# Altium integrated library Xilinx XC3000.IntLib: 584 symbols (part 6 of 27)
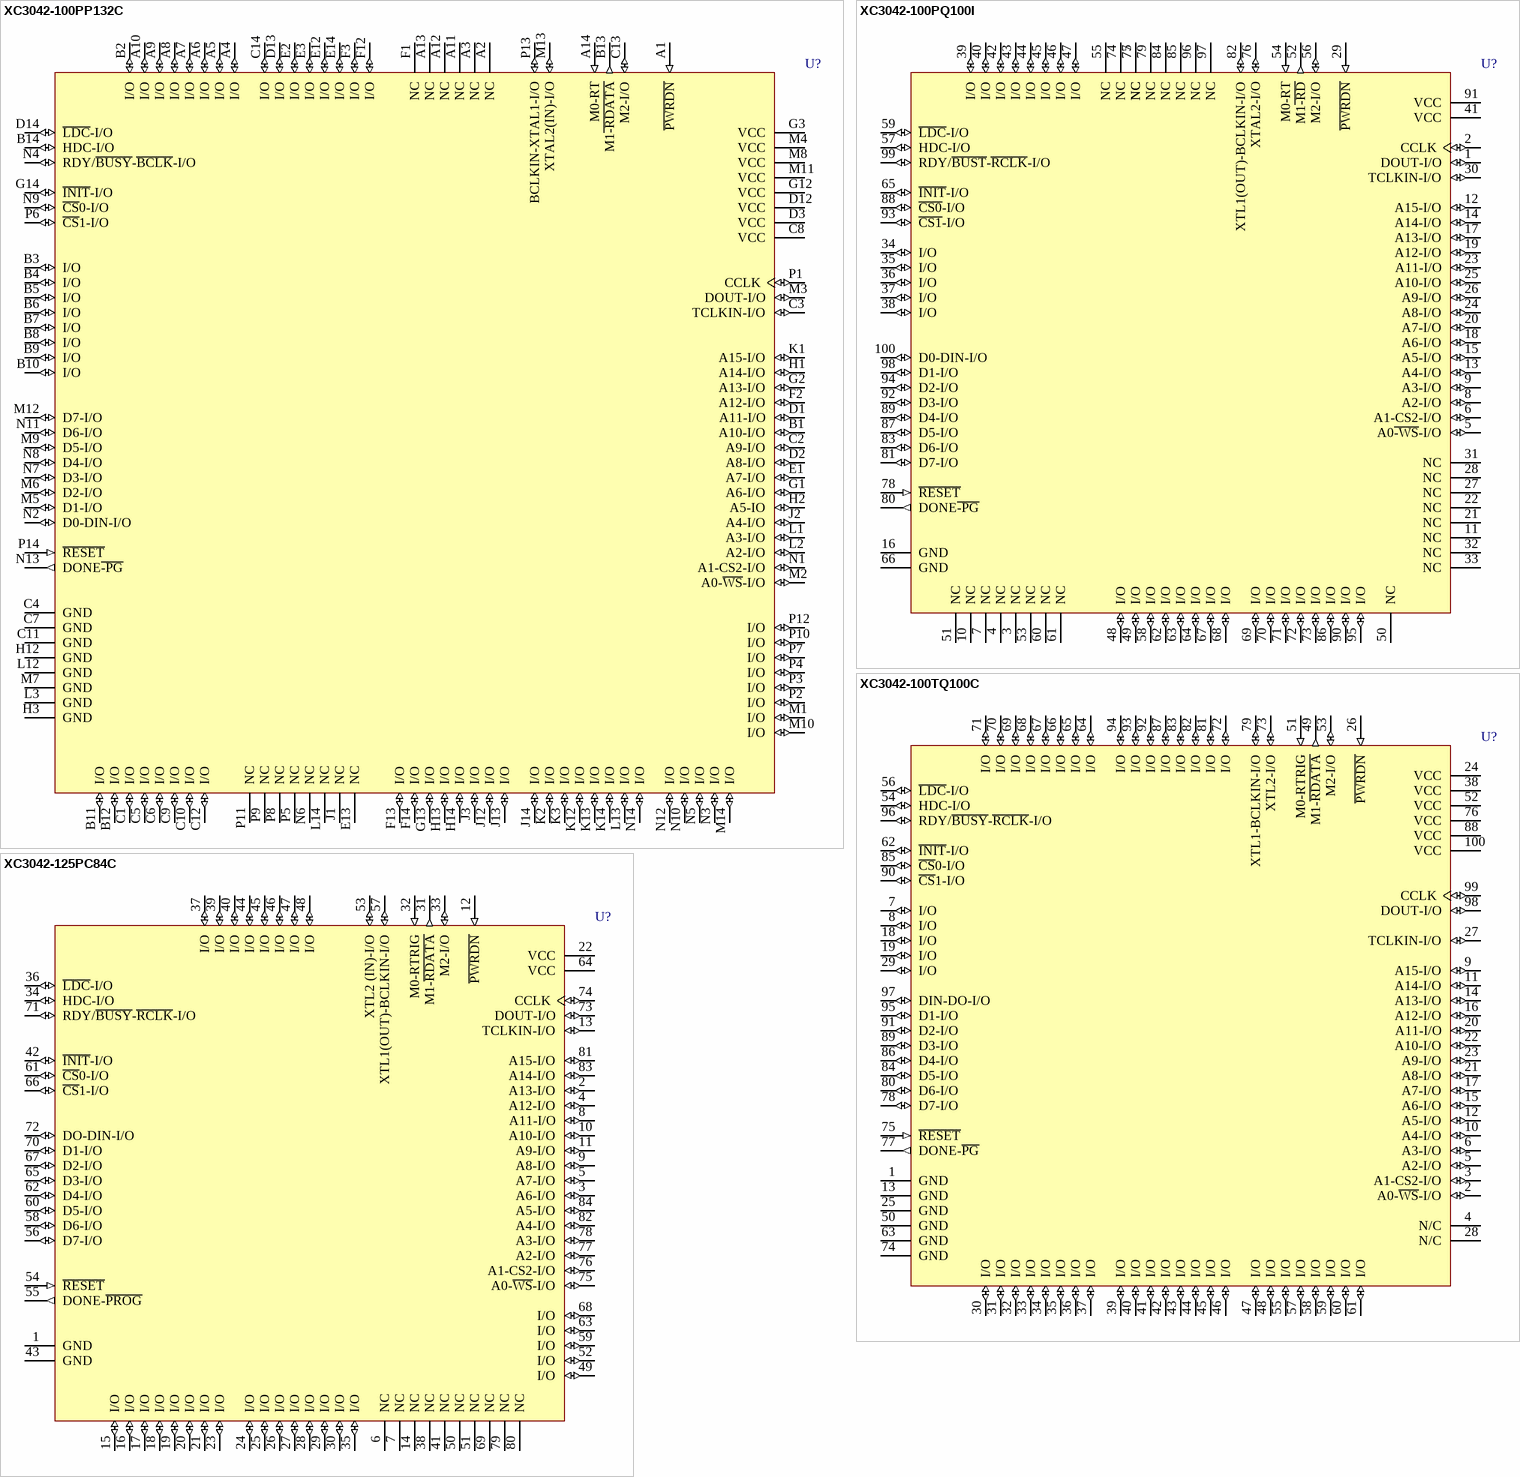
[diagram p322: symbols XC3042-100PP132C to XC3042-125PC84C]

## XC3042-100TQ100C
designator U?
Logic Cell Array with 144 CLBs, with 80 I/O Pins, 100-Pin TQFP, Commercial Grade; ComponentAvailability: Not for New Design
footprint TQ100_N (Thin QFP, 100-Leads, Body 14x14mm, Pitch 0.5mm, IPC Medium Density)
footprint TQ100_L (Thin QFP, 100-Leads, Body 14x14mm, Pitch 0.5mm, IPC High Density)
footprint TQ100_M (Thin QFP, 100-Leads, Body 14x14mm, Pitch 0.5mm, IPC Low Density)
3D model XC3042-TQ100 (100-Pin Thin Quad Flat Pack (TQ100))
pins: 1 GND (power), 2 A0-~{WS}-I/O (io), 3 A1-CS2-I/O (io), 4 N/C, 5 A2-I/O (io), 6 A3-I/O (io), 7 I/O (io), 8 I/O (io), 9 A15-I/O (io), 10 A4-I/O (io), 11 A14-I/O (io), 12 A5-I/O (io), 13 GND (power), 14 A13-I/O (io), 15 A6-I/O (io), 16 A12-I/O (io), 17 A7-I/O (io), 18 I/O (io), 19 I/O (io), 20 A11-I/O (io), 21 A8-I/O (io), 22 A10-I/O (io), 23 A9-I/O (io), 24 VCC (power), 25 GND (power), 26 ~{PWRDN} (in), 27 TCLKIN-I/O (io), 28 N/C, 29 I/O (io), 30 I/O (io), 31 I/O (io), 32 I/O (io), 33 I/O (io), 34 I/O (io), 35 I/O (io), 36 I/O (io), 37 I/O (io), 38 VCC (power), 39 I/O (io), 40 I/O (io), 41 I/O (io), 42 I/O (io), 43 I/O (io), 44 I/O (io), 45 I/O (io), 46 I/O (io), 47 I/O (io), 48 I/O (io), 49 M1-~{RDATA} (out), 50 GND (power), 51 M0-RTRIG (in), 52 VCC (power), 53 M2-I/O (io), 54 HDC-I/O (io), 55 I/O (io), 56 ~{LDC}-I/O (io), 57 I/O (io), 58 I/O (io), 59 I/O (io), 60 I/O (io), 61 I/O (io), 62 ~{INIT}-I/O (io), 63 GND (power), 64 I/O (io), 65 I/O (io), 66 I/O (io), 67 I/O (io), 68 I/O (io), 69 I/O (io), 70 I/O (io), 71 I/O (io), 72 I/O (io), 73 XTL2-I/O (io), 74 GND (power), 75 ~{RESET} (in), 76 VCC (power), 77 DONE-~{PG} (out), 78 D7-I/O (io), 79 XTL1-BCLKIN-I/O (io), 80 D6-I/O (io), 81 I/O (io), 82 I/O (io), 83 I/O (io), 84 D5-I/O (io), 85 ~{CS}0-I/O (io), 86 D4-I/O (io), 87 I/O (io), 88 VCC (power), 89 D3-I/O (io), 90 ~{CS}1-I/O (io), 91 D2-I/O (io), 92 I/O (io), 93 I/O (io), 94 I/O (io), 95 D1-I/O (io), 96 RDY/~{BUSY}-~{RCLK}-I/O (io), 97 DIN-DO-I/O (io), 98 DOUT-I/O (io), 99 CCLK (io), 100 VCC (power)

## XC3042-125PC84C
designator U?
Logic Cell Array with 144 CLBs, with 64 I/O Pins, 84-Pin PLCC, Commercial Grade; ComponentAvailability: Not for New Design
footprint PC84_N (Leaded Chip Carrier, 84-Leads, Body 29.3x29.3mm, Pitch 1.27mm, IPC Medium Density)
footprint PC84_L (Leaded Chip Carrier, 84-Leads, Body 29.3x29.3mm, Pitch 1.27mm, IPC High Density)
footprint PC84_M (Leaded Chip Carrier, 84-Leads, Body 29.3x29.3mm, Pitch 1.27mm, IPC Low Density)
3D model XC3042-PC84 (84-Pin Plastic Leaded Chip Carrier (PC84))
pins: 1 GND (power), 2 A13-I/O (io), 3 A6-I/O (io), 4 A12-I/O (io), 5 A7-I/O (io), 6 NC, 7 NC, 8 A11-I/O (io), 9 A8-I/O (io), 10 A10-I/O (io), 11 A9-I/O (io), 12 ~{PWRDN} (in), 13 TCLKIN-I/O (io), 14 NC, 15 I/O (io), 16 I/O (io), 17 I/O (io), 18 I/O (io), 19 I/O (io), 20 I/O (io), 21 I/O (io), 22 VCC (power), 23 I/O (io), 24 I/O (io), 25 I/O (io), 26 I/O (io), 27 I/O (io), 28 I/O (io), 29 I/O (io), 30 I/O (io), 31 M1-~{RDATA} (out), 32 M0-RTRIG (in), 33 M2-I/O (io), 34 HDC-I/O (io), 35 I/O (io), 36 ~{LDC}-I/O (io), 37 I/O (io), 38 NC, 39 I/O (io), 40 I/O (io), 41 NC, 42 ~{INIT}-I/O (io), 43 GND (power), 44 I/O (io), 45 I/O (io), 46 I/O (io), 47 I/O (io), 48 I/O (io), 49 I/O (io), 50 NC, 51 NC, 52 I/O (io), 53 XTL2 (IN)-I/O (io), 54 ~{RESET} (in), 55 DONE-~{PROG} (out), 56 D7-I/O (io), 57 XTL1(OUT)-BCLKIN-I/O (io), 58 D6-I/O (io), 59 I/O (io), 60 D5-I/O (io), 61 ~{CS}0-I/O (io), 62 D4-I/O (io), 63 I/O (io), 64 VCC (power), 65 D3-I/O (io), 66 ~{CS}1-I/O (io), 67 D2-I/O (io), 68 I/O (io), 69 NC, 70 D1-I/O (io), 71 RDY/~{BUSY}-~{RCLK}-I/O (io), 72 DO-DIN-I/O (io), 73 DOUT-I/O (io), 74 CCLK (io), 75 A0-~{WS}-I/O (io), 76 A1-CS2-I/O (io), 77 A2-I/O (io), 78 A3-I/O (io), 79 NC, 80 NC, 81 A15-I/O (io), 82 A4-I/O (io), 83 A14-I/O (io), 84 A5-I/O (io)

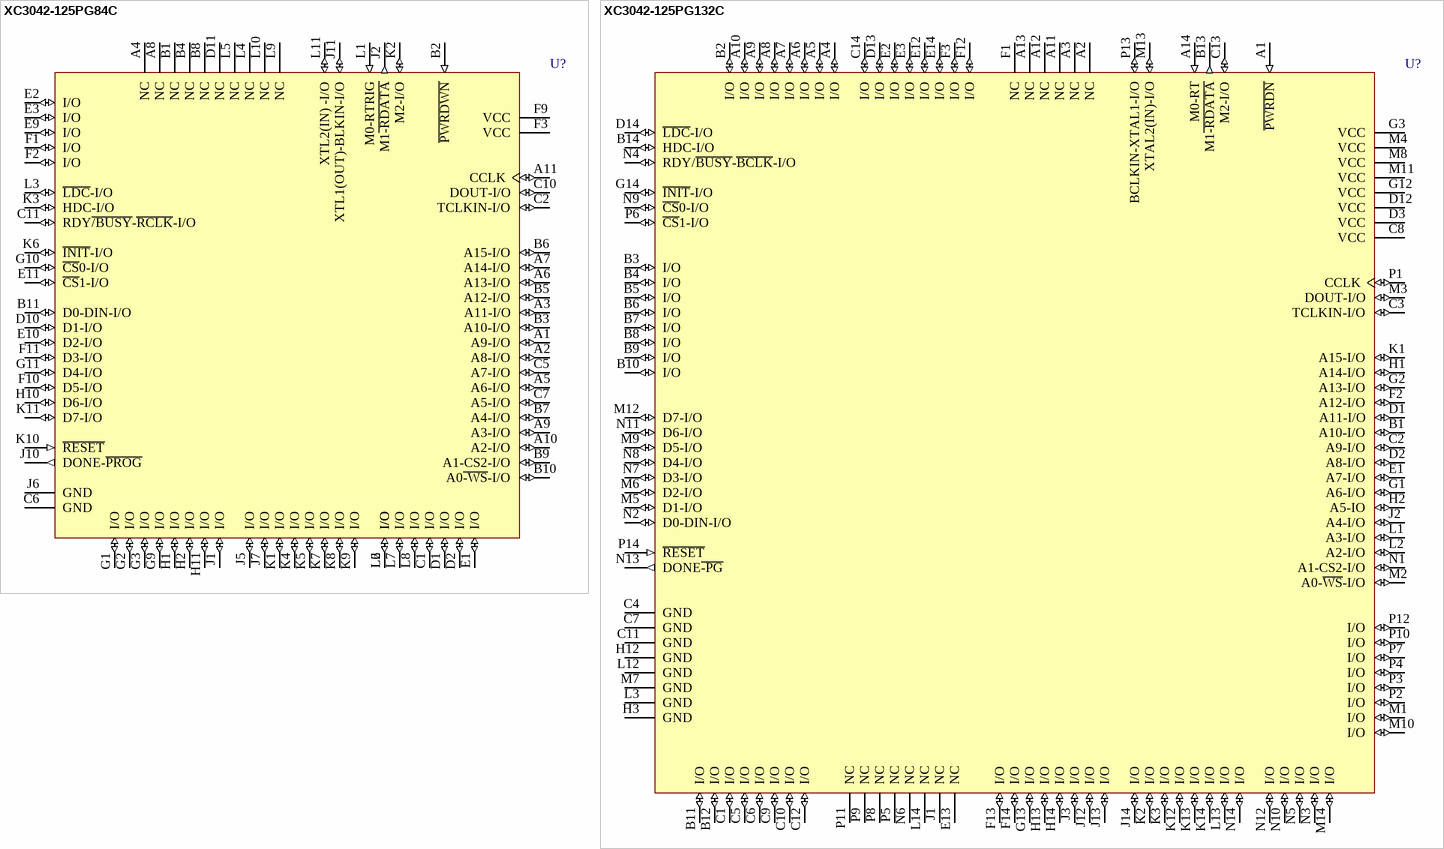
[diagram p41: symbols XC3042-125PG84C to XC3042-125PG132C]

## XC3042-125PG84C
designator U?
Logic Cell Array with 144 CLBs, with 64 I/O Pins, 84-Pin PGA, Commercial Grade; ComponentAvailability: Not for New Design
footprint PG84 (PGA, 85-Leads, Body 28x28mm, Pitch 2.54mm)
3D model XC3042-PG84 (84-Pin Ceramic Pin Grid Array (PG84))
pins: A1 A9-I/O (io), A2 A8-I/O (io), A3 A11-I/O (io), A4 NC, A5 A6-I/O (io), A6 A13-I/O (io), A7 A14-I/O (io), A8 NC, A9 A3-I/O (io), A10 A2-I/O (io), A11 CCLK (io), B1 NC, B2 ~{PWRDWN} (in), B3 A10-I/O (io), B4 NC, B5 A12-I/O (io), B6 A15-I/O (io), B7 A4-I/O (io), B8 NC, B9 A1-CS2-I/O (io), B10 A0~{-WS}-I/O (io), B11 D0-DIN-I/O (io), C1 I/O (io), C2 TCLKIN-I/O (io), C5 A7-I/O (io), C6 GND (power), C7 A5-I/O (io), C10 DOUT-I/O (io), C11 RDY~{/BUSY}-~{RCLK}-I/O (io), D1 I/O (io), D2 I/O (io), D10 D1-I/O (io), D11 NC, E1 I/O (io), E2 I/O (io), E3 I/O (io), E9 I/O (io), E10 D2-I/O (io), E11 ~{CS}1-I/O (io), F1 I/O (io), F2 I/O (io), F3 VCC (power), F9 VCC (power), F10 D5-I/O (io), F11 D3-I/O (io), G1 I/O (io), G2 I/O (io), G3 I/O (io), G9 I/O (io), G10 ~{CS}0-I/O (io), G11 D4-I/O (io), H1 I/O (io), H2 I/O (io), H10 D6-I/O (io), H11 I/O (io), J1 I/O (io), J2 M1~{-RDATA} (out), J5 I/O (io), J6 GND (power), J7 I/O (io), J10 DONE-~{PROG} (out), J11 XTL1(OUT)-BLKIN-I/O (io), K1 I/O (io), K2 M2-I/O (io), K3 HDC-I/O (io), K4 I/O (io), K5 I/O (io), K6 ~{INIT}-I/O (io), K7 I/O (io), K8 I/O (io), K9 I/O (io), K10 ~{RESET} (in), K11 D7-I/O (io), L1 M0-RTRIG (in), L2 I/O (io), L3 ~{LDC}-I/O (io), L4 NC, L5 NC, L6 I/O (io), L7 I/O (io), L8 I/O (io), L9 NC, L10 NC, L11 XTL2(IN) -I/O (io)

## XC3042-125PG132C
designator U?
Logic Cell Array with 144 CLBs, with 96 I/O Pins, 132-Pin PGA, Commercial Grade; ComponentAvailability: Not for New Design
footprint PG132 (PGA, 132-Leads, Body 37x37mm, Pitch 2.54mm)
3D model XC3042-PG132 (132-Pin Ceramic Pin Grid Array (PG132))
pins: A1 ~{PWRDN} (in), A2 NC, A3 NC, A4 I/O (io), A5 I/O (io), A6 I/O (io), A7 I/O (io), A8 I/O (io), A9 I/O (io), A10 I/O (io), A11 NC, A12 NC, A13 NC, A14 M0-RT (in), B1 A10-I/O (io), B2 I/O (io), B3 I/O (io), B4 I/O (io), B5 I/O (io), B6 I/O (io), B7 I/O (io), B8 I/O (io), B9 I/O (io), B10 I/O (io), B11 I/O (io), B12 I/O (io), B13 M1~{-RDATA} (out), B14 HDC-I/O (io), C1 I/O (io), C2 A9-I/O (io), C3 TCLKIN-I/O (io), C4 GND (power), C5 I/O (io), C6 I/O (io), C7 GND (power), C8 VCC (power), C9 I/O (io), C10 I/O (io), C11 GND (power), C12 I/O (io), C13 M2-I/O (io), C14 I/O (io), D1 A11-I/O (io), D2 A8-I/O (io), D3 VCC (power), D12 VCC (power), D13 I/O (io), D14 ~{LDC}-I/O (io), E1 A7-I/O (io), E2 I/O (io), E3 I/O (io), E12 I/O (io), E13 NC, E14 I/O (io), F1 NC, F2 A12-I/O (io), F3 I/O (io), F12 I/O (io), F13 I/O (io), F14 I/O (io), G1 A6-I/O (io), G2 A13-I/O (io), G3 VCC (power), G12 VCC (power), G13 I/O (io), G14 ~{INIT}-I/O (io), H1 A14-I/O (io), H2 A5-IO (io), H3 GND (power), H12 GND (power), H13 I/O (io), H14 I/O (io), J1 NC, J2 A4-I/O (io), J3 I/O (io), J12 I/O (io), J13 I/O (io), J14 I/O (io), K1 A15-I/O (io), K2 I/O (io), K3 I/O (io), K12 I/O (io), K13 I/O (io), K14 I/O (io), L1 A3-I/O (io), L2 A2-I/O (io), L3 GND (power), L12 GND (power), L13 I/O (io), L14 NC, M1 I/O (io), M2 A0-~{WS}-I/O (io), M3 DOUT-I/O (io), M4 VCC (power), M5 D1-I/O (io), M6 D2-I/O (io), M7 GND (power), M8 VCC (power), M9 D5-I/O (io), M10 I/O (io), M11 VCC (power), M12 D7-I/O (io), M13 XTAL2(IN)-I/O (io), M14 I/O (io), N1 A1-CS2-I/O (io), N2 D0-DIN-I/O (io), N3 I/O (io), N4 RDY/~{BUSY}-~{BCLK}-I/O (io), N5 I/O (io), N6 NC, N7 D3-I/O (io), N8 D4-I/O (io), N9 ~{CS}0-I/O (io), N10 I/O (io), N11 D6-I/O (io), N12 I/O (io), N13 DONE~{-PG} (out), N14 I/O (io), P1 CCLK (io), P2 I/O (io), P3 I/O (io), P4 I/O (io), P5 NC, P6 ~{CS}1-I/O (io), P7 I/O (io), P8 NC, P9 NC, P10 I/O (io), P11 NC, P12 I/O (io), P13 BCLKIN-XTAL1-I/O (io), P14 ~{RESET} (in)

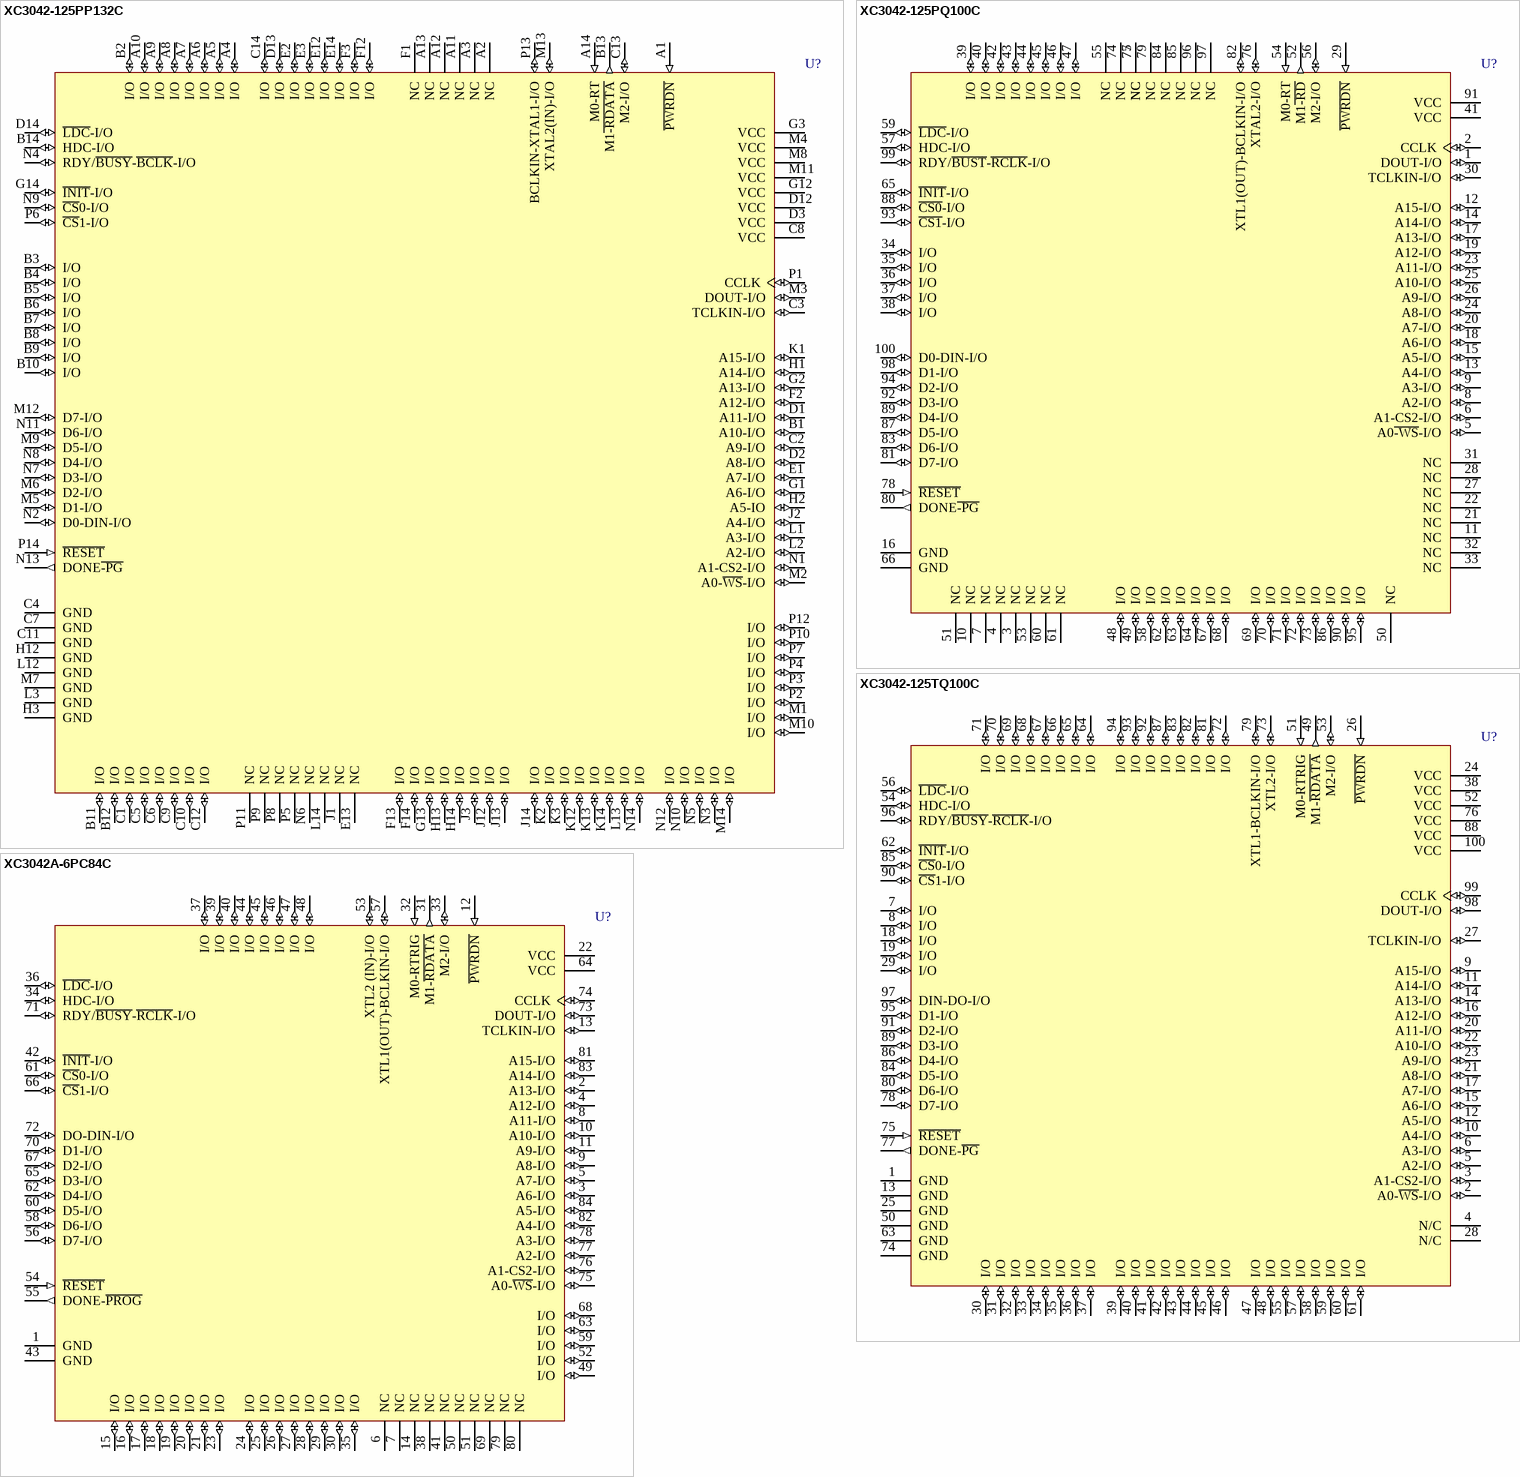
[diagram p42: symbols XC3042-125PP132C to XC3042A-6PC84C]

## XC3042-125PP132C
designator U?
Logic Cell Array with 144 CLBs, with 96 I/O Pins, 132-Pin PGA, Commercial Grade; ComponentAvailability: Not for New Design
footprint PP132 (PGA, 132-Leads, Body 37x37mm, Pitch 2.54mm)
3D model XC3042-PP132 (132-Pin Plastic Pin Grid Array (PP132))
pins: A1 ~{PWRDN} (in), A2 NC, A3 NC, A4 I/O (io), A5 I/O (io), A6 I/O (io), A7 I/O (io), A8 I/O (io), A9 I/O (io), A10 I/O (io), A11 NC, A12 NC, A13 NC, A14 M0-RT (in), B1 A10-I/O (io), B2 I/O (io), B3 I/O (io), B4 I/O (io), B5 I/O (io), B6 I/O (io), B7 I/O (io), B8 I/O (io), B9 I/O (io), B10 I/O (io), B11 I/O (io), B12 I/O (io), B13 M1~{-RDATA} (out), B14 HDC-I/O (io), C1 I/O (io), C2 A9-I/O (io), C3 TCLKIN-I/O (io), C4 GND (power), C5 I/O (io), C6 I/O (io), C7 GND (power), C8 VCC (power), C9 I/O (io), C10 I/O (io), C11 GND (power), C12 I/O (io), C13 M2-I/O (io), C14 I/O (io), D1 A11-I/O (io), D2 A8-I/O (io), D3 VCC (power), D12 VCC (power), D13 I/O (io), D14 ~{LDC}-I/O (io), E1 A7-I/O (io), E2 I/O (io), E3 I/O (io), E12 I/O (io), E13 NC, E14 I/O (io), F1 NC, F2 A12-I/O (io), F3 I/O (io), F12 I/O (io), F13 I/O (io), F14 I/O (io), G1 A6-I/O (io), G2 A13-I/O (io), G3 VCC (power), G12 VCC (power), G13 I/O (io), G14 ~{INIT}-I/O (io), H1 A14-I/O (io), H2 A5-IO (io), H3 GND (power), H12 GND (power), H13 I/O (io), H14 I/O (io), J1 NC, J2 A4-I/O (io), J3 I/O (io), J12 I/O (io), J13 I/O (io), J14 I/O (io), K1 A15-I/O (io), K2 I/O (io), K3 I/O (io), K12 I/O (io), K13 I/O (io), K14 I/O (io), L1 A3-I/O (io), L2 A2-I/O (io), L3 GND (power), L12 GND (power), L13 I/O (io), L14 NC, M1 I/O (io), M2 A0-~{WS}-I/O (io), M3 DOUT-I/O (io), M4 VCC (power), M5 D1-I/O (io), M6 D2-I/O (io), M7 GND (power), M8 VCC (power), M9 D5-I/O (io), M10 I/O (io), M11 VCC (power), M12 D7-I/O (io), M13 XTAL2(IN)-I/O (io), M14 I/O (io), N1 A1-CS2-I/O (io), N2 D0-DIN-I/O (io), N3 I/O (io), N4 RDY/~{BUSY}-~{BCLK}-I/O (io), N5 I/O (io), N6 NC, N7 D3-I/O (io), N8 D4-I/O (io), N9 ~{CS}0-I/O (io), N10 I/O (io), N11 D6-I/O (io), N12 I/O (io), N13 DONE~{-PG} (out), N14 I/O (io), P1 CCLK (io), P2 I/O (io), P3 I/O (io), P4 I/O (io), P5 NC, P6 ~{CS}1-I/O (io), P7 I/O (io), P8 NC, P9 NC, P10 I/O (io), P11 NC, P12 I/O (io), P13 BCLKIN-XTAL1-I/O (io), P14 ~{RESET} (in)

## XC3042-125PQ100C
designator U?
Logic Cell Array with 144 CLBs, with 64 I/O Pins, 100-Pin PQFP, Commercial Grade; ComponentAvailability: Not for New Design
footprint PQ100_N (QFP, 100-Leads, Body 20x14mm, Pitch 0.65mm, IPC Medium Density)
footprint PQ100_L (QFP, 100-Leads, Body 20x14mm, Pitch 0.65mm, IPC High Density)
footprint PQ100_M (QFP, 100-Leads, Body 20x14mm, Pitch 0.65mm, IPC Low Density)
3D model XC3042-PQ100 (100-Pin Plastic Quad Flat Pack (PQ100))
pins: 1 DOUT-I/O (io), 2 CCLK (io), 3 NC, 4 NC, 5 A0~{-WS}-I/O (io), 6 A1-CS2-I/O (io), 7 NC, 8 A2-I/O (io), 9 A3-I/O (io), 10 NC, 11 NC, 12 A15-I/O (io), 13 A4-I/O (io), 14 A14-I/O (io), 15 A5-I/O (io), 16 GND (power), 17 A13-I/O (io), 18 A6-I/O (io), 19 A12-I/O (io), 20 A7-I/O (io), 21 NC, 22 NC, 23 A11-I/O (io), 24 A8-I/O (io), 25 A10-I/O (io), 26 A9-I/O (io), 27 NC, 28 NC, 29 ~{PWRDN} (in), 30 TCLKIN-I/O (io), 31 NC, 32 NC, 33 NC, 34 I/O (io), 35 I/O (io), 36 I/O (io), 37 I/O (io), 38 I/O (io), 39 I/O (io), 40 I/O (io), 41 VCC (power), 42 I/O (io), 43 I/O (io), 44 I/O (io), 45 I/O (io), 46 I/O (io), 47 I/O (io), 48 I/O (io), 49 I/O (io), 50 NC, 51 NC, 52 M1~{-RD} (out), 53 NC, 54 M0-RT (in), 55 NC, 56 M2-I/O (io), 57 HDC-I/O (io), 58 I/O (io), 59 ~{LDC}-I/O (io), 60 NC, 61 NC, 62 I/O (io), 63 I/O (io), 64 I/O (io), 65 ~{INIT}-I/O (io), 66 GND (power), 67 I/O (io), 68 I/O (io), 69 I/O (io), 70 I/O (io), 71 I/O (io), 72 I/O (io), 73 I/O (io), 74 NC, 75 NC, 76 XTAL2-I/O (io), 77 NC, 78 ~{RESET} (in), 79 NC, 80 DONE~{-PG} (out), 81 D7-I/O (io), 82 XTL1(OUT)-BCLKIN-I/O (io), 83 D6-I/O (io), 84 NC, 85 NC, 86 I/O (io), 87 D5-I/O (io), 88 ~{CS0}-I/O (io), 89 D4-I/O (io), 90 I/O (io), 91 VCC (power), 92 D3-I/O (io), 93 ~{CS1}-I/O (io), 94 D2-I/O (io), 95 I/O (io), 96 NC, 97 NC, 98 D1-I/O (io), 99 RDY/~{BUST}-~{RCLK}-I/O (io), 100 D0-DIN-I/O (io)

## XC3042-125TQ100C
designator U?
Logic Cell Array with 144 CLBs, with 80 I/O Pins, 100-Pin TQFP, Commercial Grade; ComponentAvailability: Not for New Design
footprint TQ100_N (Thin QFP, 100-Leads, Body 14x14mm, Pitch 0.5mm, IPC Medium Density)
footprint TQ100_L (Thin QFP, 100-Leads, Body 14x14mm, Pitch 0.5mm, IPC High Density)
footprint TQ100_M (Thin QFP, 100-Leads, Body 14x14mm, Pitch 0.5mm, IPC Low Density)
3D model XC3042-TQ100 (100-Pin Thin Quad Flat Pack (TQ100))
pins: 1 GND (power), 2 A0-~{WS}-I/O (io), 3 A1-CS2-I/O (io), 4 N/C, 5 A2-I/O (io), 6 A3-I/O (io), 7 I/O (io), 8 I/O (io), 9 A15-I/O (io), 10 A4-I/O (io), 11 A14-I/O (io), 12 A5-I/O (io), 13 GND (power), 14 A13-I/O (io), 15 A6-I/O (io), 16 A12-I/O (io), 17 A7-I/O (io), 18 I/O (io), 19 I/O (io), 20 A11-I/O (io), 21 A8-I/O (io), 22 A10-I/O (io), 23 A9-I/O (io), 24 VCC (power), 25 GND (power), 26 ~{PWRDN} (in), 27 TCLKIN-I/O (io), 28 N/C, 29 I/O (io), 30 I/O (io), 31 I/O (io), 32 I/O (io), 33 I/O (io), 34 I/O (io), 35 I/O (io), 36 I/O (io), 37 I/O (io), 38 VCC (power), 39 I/O (io), 40 I/O (io), 41 I/O (io), 42 I/O (io), 43 I/O (io), 44 I/O (io), 45 I/O (io), 46 I/O (io), 47 I/O (io), 48 I/O (io), 49 M1-~{RDATA} (out), 50 GND (power), 51 M0-RTRIG (in), 52 VCC (power), 53 M2-I/O (io), 54 HDC-I/O (io), 55 I/O (io), 56 ~{LDC}-I/O (io), 57 I/O (io), 58 I/O (io), 59 I/O (io), 60 I/O (io), 61 I/O (io), 62 ~{INIT}-I/O (io), 63 GND (power), 64 I/O (io), 65 I/O (io), 66 I/O (io), 67 I/O (io), 68 I/O (io), 69 I/O (io), 70 I/O (io), 71 I/O (io), 72 I/O (io), 73 XTL2-I/O (io), 74 GND (power), 75 ~{RESET} (in), 76 VCC (power), 77 DONE-~{PG} (out), 78 D7-I/O (io), 79 XTL1-BCLKIN-I/O (io), 80 D6-I/O (io), 81 I/O (io), 82 I/O (io), 83 I/O (io), 84 D5-I/O (io), 85 ~{CS}0-I/O (io), 86 D4-I/O (io), 87 I/O (io), 88 VCC (power), 89 D3-I/O (io), 90 ~{CS}1-I/O (io), 91 D2-I/O (io), 92 I/O (io), 93 I/O (io), 94 I/O (io), 95 D1-I/O (io), 96 RDY/~{BUSY}-~{RCLK}-I/O (io), 97 DIN-DO-I/O (io), 98 DOUT-I/O (io), 99 CCLK (io), 100 VCC (power)

## XC3042A-6PC84C
designator U?
Logic Cell Array with 144 CLBs, with 64 I/O Pins, 84-Pin PLCC, Commercial Grade; ComponentAvailability: Not for New Design
footprint PC84_N (Leaded Chip Carrier, 84-Leads, Body 29.3x29.3mm, Pitch 1.27mm, IPC Medium Density)
footprint PC84_L (Leaded Chip Carrier, 84-Leads, Body 29.3x29.3mm, Pitch 1.27mm, IPC High Density)
footprint PC84_M (Leaded Chip Carrier, 84-Leads, Body 29.3x29.3mm, Pitch 1.27mm, IPC Low Density)
3D model XC3042A-PC84 (84-Pin Plastic Leaded Chip Carrier (PC84))
pins: 1 GND (power), 2 A13-I/O (io), 3 A6-I/O (io), 4 A12-I/O (io), 5 A7-I/O (io), 6 NC, 7 NC, 8 A11-I/O (io), 9 A8-I/O (io), 10 A10-I/O (io), 11 A9-I/O (io), 12 ~{PWRDN} (in), 13 TCLKIN-I/O (io), 14 NC, 15 I/O (io), 16 I/O (io), 17 I/O (io), 18 I/O (io), 19 I/O (io), 20 I/O (io), 21 I/O (io), 22 VCC (power), 23 I/O (io), 24 I/O (io), 25 I/O (io), 26 I/O (io), 27 I/O (io), 28 I/O (io), 29 I/O (io), 30 I/O (io), 31 M1-~{RDATA} (out), 32 M0-RTRIG (in), 33 M2-I/O (io), 34 HDC-I/O (io), 35 I/O (io), 36 ~{LDC}-I/O (io), 37 I/O (io), 38 NC, 39 I/O (io), 40 I/O (io), 41 NC, 42 ~{INIT}-I/O (io), 43 GND (power), 44 I/O (io), 45 I/O (io), 46 I/O (io), 47 I/O (io), 48 I/O (io), 49 I/O (io), 50 NC, 51 NC, 52 I/O (io), 53 XTL2 (IN)-I/O (io), 54 ~{RESET} (in), 55 DONE-~{PROG} (out), 56 D7-I/O (io), 57 XTL1(OUT)-BCLKIN-I/O (io), 58 D6-I/O (io), 59 I/O (io), 60 D5-I/O (io), 61 ~{CS}0-I/O (io), 62 D4-I/O (io), 63 I/O (io), 64 VCC (power), 65 D3-I/O (io), 66 ~{CS}1-I/O (io), 67 D2-I/O (io), 68 I/O (io), 69 NC, 70 D1-I/O (io), 71 RDY/~{BUSY}-~{RCLK}-I/O (io), 72 DO-DIN-I/O (io), 73 DOUT-I/O (io), 74 CCLK (io), 75 A0-~{WS}-I/O (io), 76 A1-CS2-I/O (io), 77 A2-I/O (io), 78 A3-I/O (io), 79 NC, 80 NC, 81 A15-I/O (io), 82 A4-I/O (io), 83 A14-I/O (io), 84 A5-I/O (io)

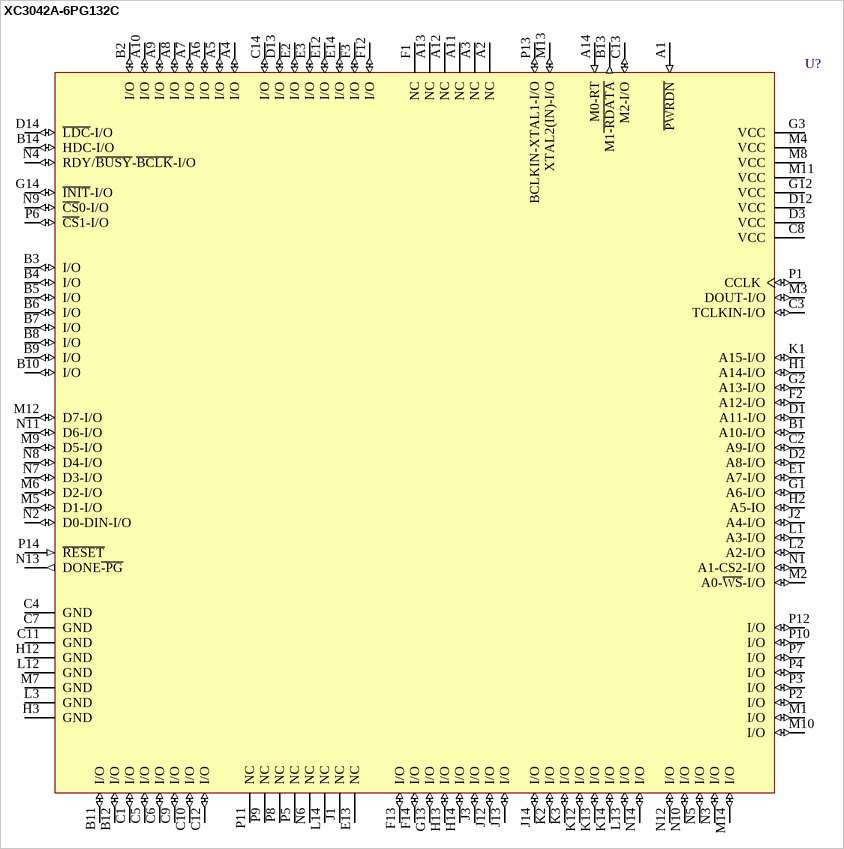
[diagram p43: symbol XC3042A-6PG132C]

## XC3042A-6PG132C
designator U?
Logic Cell Array with 144 CLBs, with 96 I/O Pins, 132-Pin PGA, Commercial Grade; ComponentAvailability: Not for New Design
footprint PG132 (PGA, 132-Leads, Body 37x37mm, Pitch 2.54mm)
3D model XC3042A-PG132 (132-Pin Ceramic Pin Grid Array (PG132))
pins: A1 ~{PWRDN} (in), A2 NC, A3 NC, A4 I/O (io), A5 I/O (io), A6 I/O (io), A7 I/O (io), A8 I/O (io), A9 I/O (io), A10 I/O (io), A11 NC, A12 NC, A13 NC, A14 M0-RT (in), B1 A10-I/O (io), B2 I/O (io), B3 I/O (io), B4 I/O (io), B5 I/O (io), B6 I/O (io), B7 I/O (io), B8 I/O (io), B9 I/O (io), B10 I/O (io), B11 I/O (io), B12 I/O (io), B13 M1~{-RDATA} (out), B14 HDC-I/O (io), C1 I/O (io), C2 A9-I/O (io), C3 TCLKIN-I/O (io), C4 GND (power), C5 I/O (io), C6 I/O (io), C7 GND (power), C8 VCC (power), C9 I/O (io), C10 I/O (io), C11 GND (power), C12 I/O (io), C13 M2-I/O (io), C14 I/O (io), D1 A11-I/O (io), D2 A8-I/O (io), D3 VCC (power), D12 VCC (power), D13 I/O (io), D14 ~{LDC}-I/O (io), E1 A7-I/O (io), E2 I/O (io), E3 I/O (io), E12 I/O (io), E13 NC, E14 I/O (io), F1 NC, F2 A12-I/O (io), F3 I/O (io), F12 I/O (io), F13 I/O (io), F14 I/O (io), G1 A6-I/O (io), G2 A13-I/O (io), G3 VCC (power), G12 VCC (power), G13 I/O (io), G14 ~{INIT}-I/O (io), H1 A14-I/O (io), H2 A5-IO (io), H3 GND (power), H12 GND (power), H13 I/O (io), H14 I/O (io), J1 NC, J2 A4-I/O (io), J3 I/O (io), J12 I/O (io), J13 I/O (io), J14 I/O (io), K1 A15-I/O (io), K2 I/O (io), K3 I/O (io), K12 I/O (io), K13 I/O (io), K14 I/O (io), L1 A3-I/O (io), L2 A2-I/O (io), L3 GND (power), L12 GND (power), L13 I/O (io), L14 NC, M1 I/O (io), M2 A0-~{WS}-I/O (io), M3 DOUT-I/O (io), M4 VCC (power), M5 D1-I/O (io), M6 D2-I/O (io), M7 GND (power), M8 VCC (power), M9 D5-I/O (io), M10 I/O (io), M11 VCC (power), M12 D7-I/O (io), M13 XTAL2(IN)-I/O (io), M14 I/O (io), N1 A1-CS2-I/O (io), N2 D0-DIN-I/O (io), N3 I/O (io), N4 RDY/~{BUSY}-~{BCLK}-I/O (io), N5 I/O (io), N6 NC, N7 D3-I/O (io), N8 D4-I/O (io), N9 ~{CS}0-I/O (io), N10 I/O (io), N11 D6-I/O (io), N12 I/O (io), N13 DONE~{-PG} (out), N14 I/O (io), P1 CCLK (io), P2 I/O (io), P3 I/O (io), P4 I/O (io), P5 NC, P6 ~{CS}1-I/O (io), P7 I/O (io), P8 NC, P9 NC, P10 I/O (io), P11 NC, P12 I/O (io), P13 BCLKIN-XTAL1-I/O (io), P14 ~{RESET} (in)

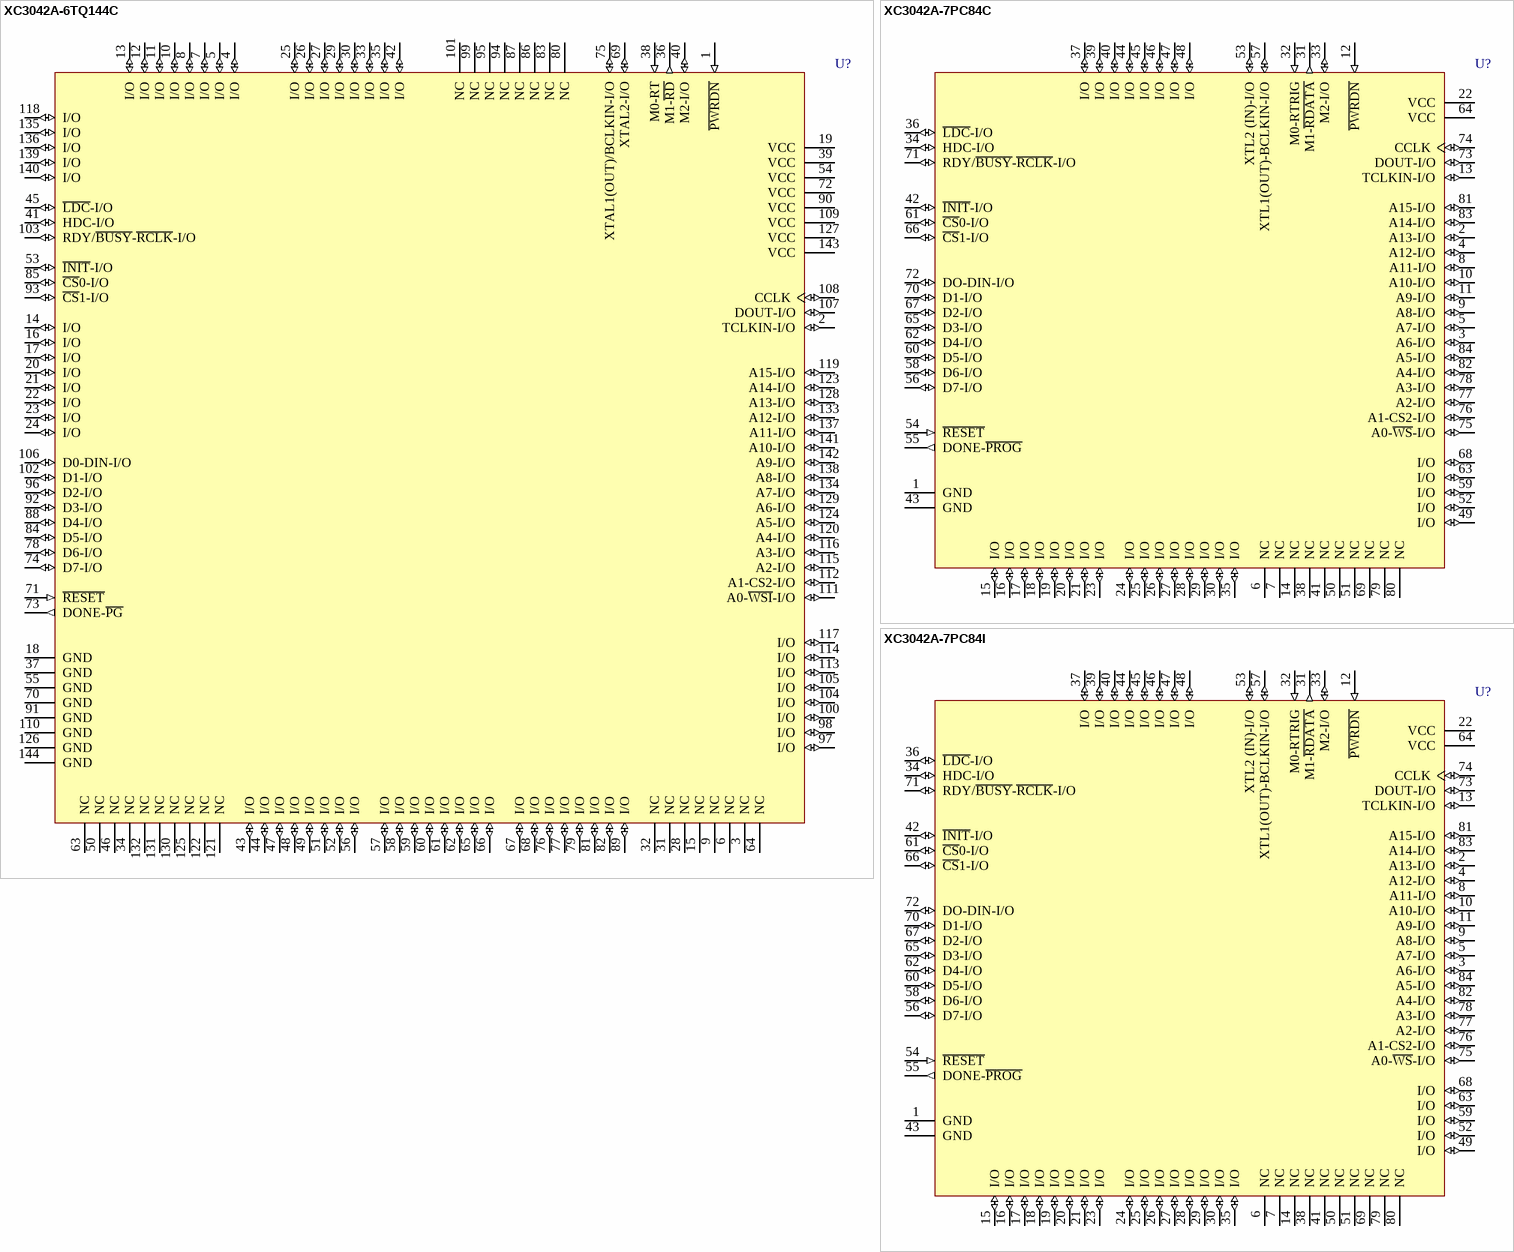
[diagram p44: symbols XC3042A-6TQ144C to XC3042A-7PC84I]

## XC3042A-6TQ144C
designator U?
Logic Cell Array with 144 CLBs, with 96 I/O Pinds, 144-Pin TQFP, Commercial Grade; ComponentAvailability: Not for New Design
footprint TQ144_N (Thin QFP, 144-Leads, Body 20x20mm, Pitch 0.5mm, IPC Medium Density)
footprint TQ144_L (Thin QFP, 144-Leads, Body 20x20mm, Pitch 0.5mm, IPC High Density)
footprint TQ144_M (Thin QFP, 144-Leads, Body 20x20mm, Pitch 0.5mm, IPC Low Density)
3D model XC3042A-TQ144 (144-Pin Thin Quad Flat Pack (TQ144))
pins: 1 ~{PWRDN} (in), 2 TCLKIN-I/O (io), 3 NC, 4 I/O (io), 5 I/O (io), 6 NC, 7 I/O (io), 8 I/O (io), 9 NC, 10 I/O (io), 11 I/O (io), 12 I/O (io), 13 I/O (io), 14 I/O (io), 15 NC, 16 I/O (io), 17 I/O (io), 18 GND (power), 19 VCC (power), 20 I/O (io), 21 I/O (io), 22 I/O (io), 23 I/O (io), 24 I/O (io), 25 I/O (io), 26 I/O (io), 27 I/O (io), 28 NC, 29 I/O (io), 30 I/O (io), 31 NC, 32 NC, 33 I/O (io), 34 NC, 35 I/O (io), 36 M1-~{RD} (out), 37 GND (power), 38 M0-RT (in), 39 VCC (power), 40 M2-I/O (io), 41 HDC-I/O (io), 42 I/O (io), 43 I/O (io), 44 I/O (io), 45 ~{LDC}-I/O (io), 46 NC, 47 I/O (io), 48 I/O (io), 49 I/O (io), 50 NC, 51 I/O (io), 52 I/O (io), 53 ~{INIT}-I/O (io), 54 VCC (power), 55 GND (power), 56 I/O (io), 57 I/O (io), 58 I/O (io), 59 I/O (io), 60 I/O (io), 61 I/O (io), 62 I/O (io), 63 NC, 64 NC, 65 I/O (io), 66 I/O (io), 67 I/O (io), 68 I/O (io), 69 XTAL2-I/O (io), 70 GND (power), 71 ~{RESET} (in), 72 VCC (power), 73 DONE-~{PG} (out), 74 D7-I/O (io), 75 XTAL1(OUT)/BCLKIN-I/O (io), 76 I/O (io), 77 I/O (io), 78 D6-I/O (io), 79 I/O (io), 80 NC, 81 I/O (io), 82 I/O (io), 83 NC, 84 D5-I/O (io), 85 ~{CS}0-I/O (io), 86 NC, 87 NC, 88 D4-I/O (io), 89 I/O (io), 90 VCC (power), 91 GND (power), 92 D3-I/O (io), 93 ~{CS}1-I/O (io), 94 NC, 95 NC, 96 D2-I/O (io), 97 I/O (io), 98 I/O (io), 99 NC, 100 I/O (io), 101 NC, 102 D1-I/O (io), 103 RDY/~{BUSY}-~{RCLK}-I/O (io), 104 I/O (io), 105 I/O (io), 106 D0-DIN-I/O (io), 107 DOUT-I/O (io), 108 CCLK (io), 109 VCC (power), 110 GND (power), 111 A0-~{WSI}-I/O (io), 112 A1-CS2-I/O (io), 113 I/O (io), 114 I/O (io), 115 A2-I/O (io), 116 A3-I/O (io), 117 I/O (io), 118 I/O (io), 119 A15-I/O (io), 120 A4-I/O (io), 121 NC, 122 NC, 123 A14-I/O (io), 124 A5-I/O (io), 125 NC, 126 GND (power), 127 VCC (power), 128 A13-I/O (io), 129 A6-I/O (io), 130 NC, 131 NC, 132 NC, 133 A12-I/O (io), 134 A7-I/O (io), 135 I/O (io), 136 I/O (io), 137 A11-I/O (io), 138 A8-I/O (io), 139 I/O (io), 140 I/O (io), 141 A10-I/O (io), 142 A9-I/O (io), 143 VCC (power), 144 GND (power)

## XC3042A-7PC84C
designator U?
Logic Cell Array with 144 CLBs, with 64 I/O Pins, 84-Pin PLCC, Commercial Grade; ComponentAvailability: Not for New Design
footprint PC84_N (Leaded Chip Carrier, 84-Leads, Body 29.3x29.3mm, Pitch 1.27mm, IPC Medium Density)
footprint PC84_L (Leaded Chip Carrier, 84-Leads, Body 29.3x29.3mm, Pitch 1.27mm, IPC High Density)
footprint PC84_M (Leaded Chip Carrier, 84-Leads, Body 29.3x29.3mm, Pitch 1.27mm, IPC Low Density)
3D model XC3042A-PC84 (84-Pin Plastic Leaded Chip Carrier (PC84))
pins: 1 GND (power), 2 A13-I/O (io), 3 A6-I/O (io), 4 A12-I/O (io), 5 A7-I/O (io), 6 NC, 7 NC, 8 A11-I/O (io), 9 A8-I/O (io), 10 A10-I/O (io), 11 A9-I/O (io), 12 ~{PWRDN} (in), 13 TCLKIN-I/O (io), 14 NC, 15 I/O (io), 16 I/O (io), 17 I/O (io), 18 I/O (io), 19 I/O (io), 20 I/O (io), 21 I/O (io), 22 VCC (power), 23 I/O (io), 24 I/O (io), 25 I/O (io), 26 I/O (io), 27 I/O (io), 28 I/O (io), 29 I/O (io), 30 I/O (io), 31 M1-~{RDATA} (out), 32 M0-RTRIG (in), 33 M2-I/O (io), 34 HDC-I/O (io), 35 I/O (io), 36 ~{LDC}-I/O (io), 37 I/O (io), 38 NC, 39 I/O (io), 40 I/O (io), 41 NC, 42 ~{INIT}-I/O (io), 43 GND (power), 44 I/O (io), 45 I/O (io), 46 I/O (io), 47 I/O (io), 48 I/O (io), 49 I/O (io), 50 NC, 51 NC, 52 I/O (io), 53 XTL2 (IN)-I/O (io), 54 ~{RESET} (in), 55 DONE-~{PROG} (out), 56 D7-I/O (io), 57 XTL1(OUT)-BCLKIN-I/O (io), 58 D6-I/O (io), 59 I/O (io), 60 D5-I/O (io), 61 ~{CS}0-I/O (io), 62 D4-I/O (io), 63 I/O (io), 64 VCC (power), 65 D3-I/O (io), 66 ~{CS}1-I/O (io), 67 D2-I/O (io), 68 I/O (io), 69 NC, 70 D1-I/O (io), 71 RDY/~{BUSY}-~{RCLK}-I/O (io), 72 DO-DIN-I/O (io), 73 DOUT-I/O (io), 74 CCLK (io), 75 A0-~{WS}-I/O (io), 76 A1-CS2-I/O (io), 77 A2-I/O (io), 78 A3-I/O (io), 79 NC, 80 NC, 81 A15-I/O (io), 82 A4-I/O (io), 83 A14-I/O (io), 84 A5-I/O (io)

## XC3042A-7PC84I
designator U?
Logic Cell Array with 144 CLBs, with 64 I/O Pins, 84-Pin PLCC, Industrial Grade; ComponentAvailability: Not for New Design
footprint PC84_N (Leaded Chip Carrier, 84-Leads, Body 29.3x29.3mm, Pitch 1.27mm, IPC Medium Density)
footprint PC84_L (Leaded Chip Carrier, 84-Leads, Body 29.3x29.3mm, Pitch 1.27mm, IPC High Density)
footprint PC84_M (Leaded Chip Carrier, 84-Leads, Body 29.3x29.3mm, Pitch 1.27mm, IPC Low Density)
3D model XC3042A-PC84 (84-Pin Plastic Leaded Chip Carrier (PC84))
pins: 1 GND (power), 2 A13-I/O (io), 3 A6-I/O (io), 4 A12-I/O (io), 5 A7-I/O (io), 6 NC, 7 NC, 8 A11-I/O (io), 9 A8-I/O (io), 10 A10-I/O (io), 11 A9-I/O (io), 12 ~{PWRDN} (in), 13 TCLKIN-I/O (io), 14 NC, 15 I/O (io), 16 I/O (io), 17 I/O (io), 18 I/O (io), 19 I/O (io), 20 I/O (io), 21 I/O (io), 22 VCC (power), 23 I/O (io), 24 I/O (io), 25 I/O (io), 26 I/O (io), 27 I/O (io), 28 I/O (io), 29 I/O (io), 30 I/O (io), 31 M1-~{RDATA} (out), 32 M0-RTRIG (in), 33 M2-I/O (io), 34 HDC-I/O (io), 35 I/O (io), 36 ~{LDC}-I/O (io), 37 I/O (io), 38 NC, 39 I/O (io), 40 I/O (io), 41 NC, 42 ~{INIT}-I/O (io), 43 GND (power), 44 I/O (io), 45 I/O (io), 46 I/O (io), 47 I/O (io), 48 I/O (io), 49 I/O (io), 50 NC, 51 NC, 52 I/O (io), 53 XTL2 (IN)-I/O (io), 54 ~{RESET} (in), 55 DONE-~{PROG} (out), 56 D7-I/O (io), 57 XTL1(OUT)-BCLKIN-I/O (io), 58 D6-I/O (io), 59 I/O (io), 60 D5-I/O (io), 61 ~{CS}0-I/O (io), 62 D4-I/O (io), 63 I/O (io), 64 VCC (power), 65 D3-I/O (io), 66 ~{CS}1-I/O (io), 67 D2-I/O (io), 68 I/O (io), 69 NC, 70 D1-I/O (io), 71 RDY/~{BUSY}-~{RCLK}-I/O (io), 72 DO-DIN-I/O (io), 73 DOUT-I/O (io), 74 CCLK (io), 75 A0-~{WS}-I/O (io), 76 A1-CS2-I/O (io), 77 A2-I/O (io), 78 A3-I/O (io), 79 NC, 80 NC, 81 A15-I/O (io), 82 A4-I/O (io), 83 A14-I/O (io), 84 A5-I/O (io)

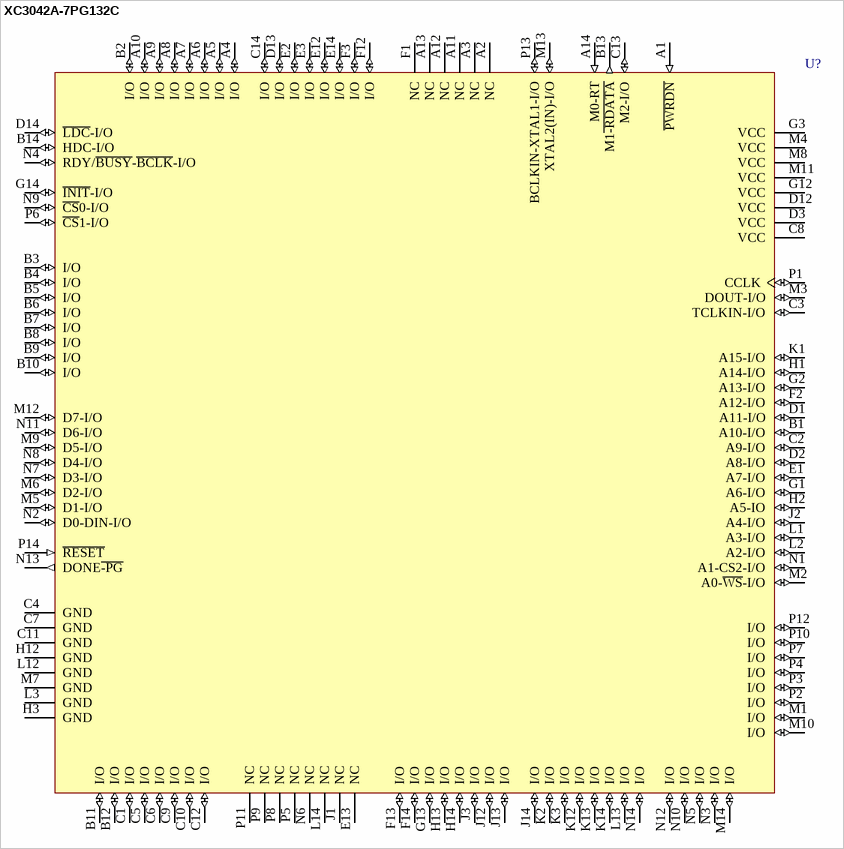
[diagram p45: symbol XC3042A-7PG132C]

## XC3042A-7PG132C
designator U?
Logic Cell Array with 144 CLBs, with 96 I/O Pins, 132-Pin PGA, Commercial Grade; ComponentAvailability: Not for New Design
footprint PG132 (PGA, 132-Leads, Body 37x37mm, Pitch 2.54mm)
3D model XC3042A-PG132 (132-Pin Ceramic Pin Grid Array (PG132))
pins: A1 ~{PWRDN} (in), A2 NC, A3 NC, A4 I/O (io), A5 I/O (io), A6 I/O (io), A7 I/O (io), A8 I/O (io), A9 I/O (io), A10 I/O (io), A11 NC, A12 NC, A13 NC, A14 M0-RT (in), B1 A10-I/O (io), B2 I/O (io), B3 I/O (io), B4 I/O (io), B5 I/O (io), B6 I/O (io), B7 I/O (io), B8 I/O (io), B9 I/O (io), B10 I/O (io), B11 I/O (io), B12 I/O (io), B13 M1~{-RDATA} (out), B14 HDC-I/O (io), C1 I/O (io), C2 A9-I/O (io), C3 TCLKIN-I/O (io), C4 GND (power), C5 I/O (io), C6 I/O (io), C7 GND (power), C8 VCC (power), C9 I/O (io), C10 I/O (io), C11 GND (power), C12 I/O (io), C13 M2-I/O (io), C14 I/O (io), D1 A11-I/O (io), D2 A8-I/O (io), D3 VCC (power), D12 VCC (power), D13 I/O (io), D14 ~{LDC}-I/O (io), E1 A7-I/O (io), E2 I/O (io), E3 I/O (io), E12 I/O (io), E13 NC, E14 I/O (io), F1 NC, F2 A12-I/O (io), F3 I/O (io), F12 I/O (io), F13 I/O (io), F14 I/O (io), G1 A6-I/O (io), G2 A13-I/O (io), G3 VCC (power), G12 VCC (power), G13 I/O (io), G14 ~{INIT}-I/O (io), H1 A14-I/O (io), H2 A5-IO (io), H3 GND (power), H12 GND (power), H13 I/O (io), H14 I/O (io), J1 NC, J2 A4-I/O (io), J3 I/O (io), J12 I/O (io), J13 I/O (io), J14 I/O (io), K1 A15-I/O (io), K2 I/O (io), K3 I/O (io), K12 I/O (io), K13 I/O (io), K14 I/O (io), L1 A3-I/O (io), L2 A2-I/O (io), L3 GND (power), L12 GND (power), L13 I/O (io), L14 NC, M1 I/O (io), M2 A0-~{WS}-I/O (io), M3 DOUT-I/O (io), M4 VCC (power), M5 D1-I/O (io), M6 D2-I/O (io), M7 GND (power), M8 VCC (power), M9 D5-I/O (io), M10 I/O (io), M11 VCC (power), M12 D7-I/O (io), M13 XTAL2(IN)-I/O (io), M14 I/O (io), N1 A1-CS2-I/O (io), N2 D0-DIN-I/O (io), N3 I/O (io), N4 RDY/~{BUSY}-~{BCLK}-I/O (io), N5 I/O (io), N6 NC, N7 D3-I/O (io), N8 D4-I/O (io), N9 ~{CS}0-I/O (io), N10 I/O (io), N11 D6-I/O (io), N12 I/O (io), N13 DONE~{-PG} (out), N14 I/O (io), P1 CCLK (io), P2 I/O (io), P3 I/O (io), P4 I/O (io), P5 NC, P6 ~{CS}1-I/O (io), P7 I/O (io), P8 NC, P9 NC, P10 I/O (io), P11 NC, P12 I/O (io), P13 BCLKIN-XTAL1-I/O (io), P14 ~{RESET} (in)

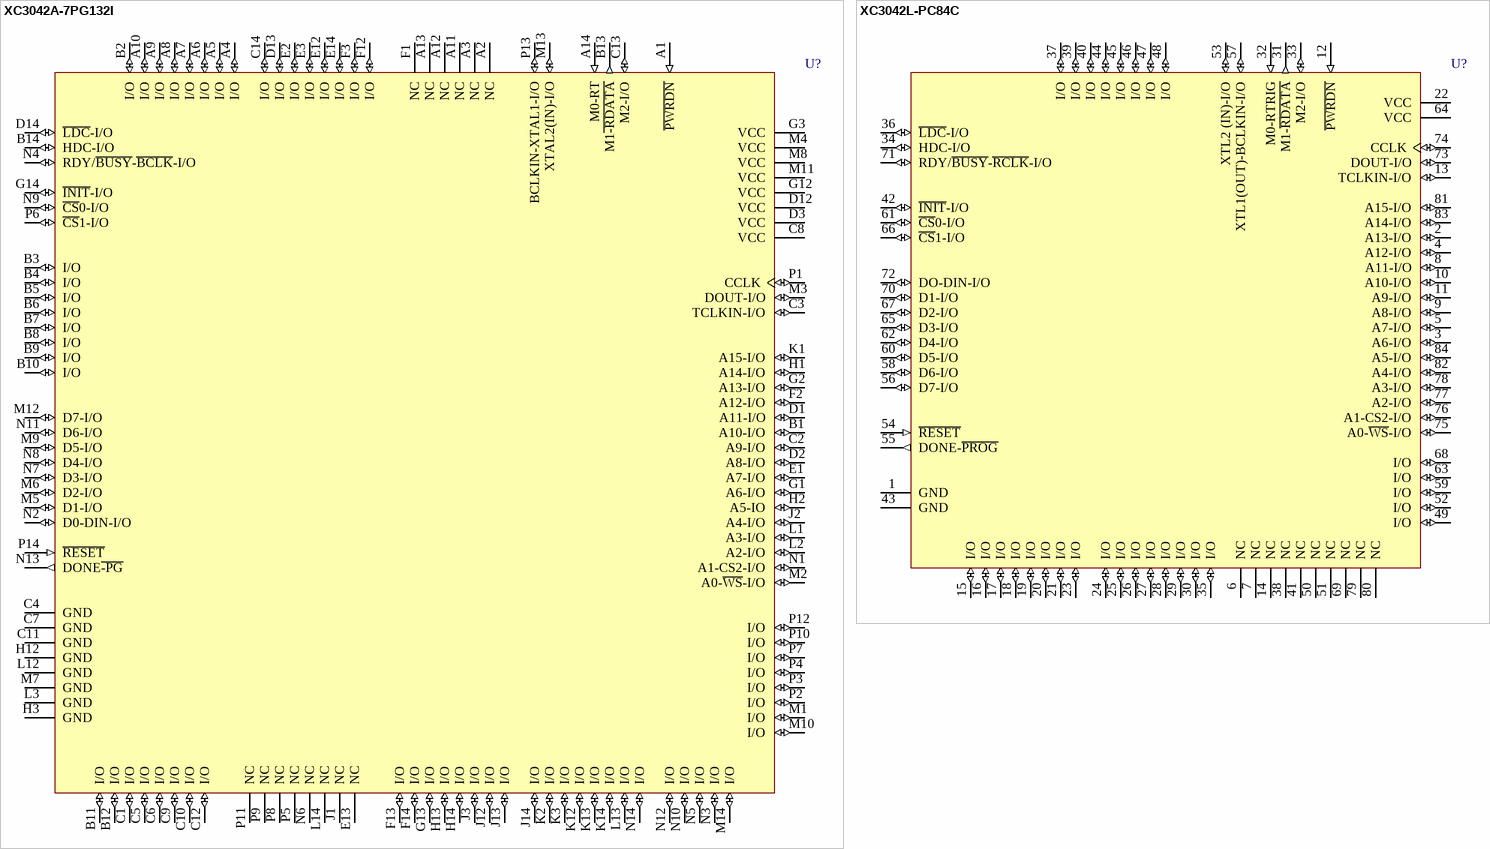
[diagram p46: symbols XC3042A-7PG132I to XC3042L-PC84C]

## XC3042A-7PG132I
designator U?
Logic Cell Array with 144 CLBs, with 96 I/O Pins, 132-Pin PGA, Industrial Grade; ComponentAvailability: Not for New Design
footprint PG132 (PGA, 132-Leads, Body 37x37mm, Pitch 2.54mm)
3D model XC3042A-PG132 (132-Pin Ceramic Pin Grid Array (PG132))
pins: A1 ~{PWRDN} (in), A2 NC, A3 NC, A4 I/O (io), A5 I/O (io), A6 I/O (io), A7 I/O (io), A8 I/O (io), A9 I/O (io), A10 I/O (io), A11 NC, A12 NC, A13 NC, A14 M0-RT (in), B1 A10-I/O (io), B2 I/O (io), B3 I/O (io), B4 I/O (io), B5 I/O (io), B6 I/O (io), B7 I/O (io), B8 I/O (io), B9 I/O (io), B10 I/O (io), B11 I/O (io), B12 I/O (io), B13 M1~{-RDATA} (out), B14 HDC-I/O (io), C1 I/O (io), C2 A9-I/O (io), C3 TCLKIN-I/O (io), C4 GND (power), C5 I/O (io), C6 I/O (io), C7 GND (power), C8 VCC (power), C9 I/O (io), C10 I/O (io), C11 GND (power), C12 I/O (io), C13 M2-I/O (io), C14 I/O (io), D1 A11-I/O (io), D2 A8-I/O (io), D3 VCC (power), D12 VCC (power), D13 I/O (io), D14 ~{LDC}-I/O (io), E1 A7-I/O (io), E2 I/O (io), E3 I/O (io), E12 I/O (io), E13 NC, E14 I/O (io), F1 NC, F2 A12-I/O (io), F3 I/O (io), F12 I/O (io), F13 I/O (io), F14 I/O (io), G1 A6-I/O (io), G2 A13-I/O (io), G3 VCC (power), G12 VCC (power), G13 I/O (io), G14 ~{INIT}-I/O (io), H1 A14-I/O (io), H2 A5-IO (io), H3 GND (power), H12 GND (power), H13 I/O (io), H14 I/O (io), J1 NC, J2 A4-I/O (io), J3 I/O (io), J12 I/O (io), J13 I/O (io), J14 I/O (io), K1 A15-I/O (io), K2 I/O (io), K3 I/O (io), K12 I/O (io), K13 I/O (io), K14 I/O (io), L1 A3-I/O (io), L2 A2-I/O (io), L3 GND (power), L12 GND (power), L13 I/O (io), L14 NC, M1 I/O (io), M2 A0-~{WS}-I/O (io), M3 DOUT-I/O (io), M4 VCC (power), M5 D1-I/O (io), M6 D2-I/O (io), M7 GND (power), M8 VCC (power), M9 D5-I/O (io), M10 I/O (io), M11 VCC (power), M12 D7-I/O (io), M13 XTAL2(IN)-I/O (io), M14 I/O (io), N1 A1-CS2-I/O (io), N2 D0-DIN-I/O (io), N3 I/O (io), N4 RDY/~{BUSY}-~{BCLK}-I/O (io), N5 I/O (io), N6 NC, N7 D3-I/O (io), N8 D4-I/O (io), N9 ~{CS}0-I/O (io), N10 I/O (io), N11 D6-I/O (io), N12 I/O (io), N13 DONE~{-PG} (out), N14 I/O (io), P1 CCLK (io), P2 I/O (io), P3 I/O (io), P4 I/O (io), P5 NC, P6 ~{CS}1-I/O (io), P7 I/O (io), P8 NC, P9 NC, P10 I/O (io), P11 NC, P12 I/O (io), P13 BCLKIN-XTAL1-I/O (io), P14 ~{RESET} (in)

## XC3042L-PC84C
designator U?
Logic Cell Array with 144 CLBs, with 64 I/O Pins, 84-Pin PLCC, Commercial Grade; ComponentAvailability: Not for New Design
footprint PC84_N (Leaded Chip Carrier, 84-Leads, Body 29.3x29.3mm, Pitch 1.27mm, IPC Medium Density)
footprint PC84_L (Leaded Chip Carrier, 84-Leads, Body 29.3x29.3mm, Pitch 1.27mm, IPC High Density)
footprint PC84_M (Leaded Chip Carrier, 84-Leads, Body 29.3x29.3mm, Pitch 1.27mm, IPC Low Density)
3D model XC3042L-PC84 (84-Pin Plastic Leaded Chip Carrier (PC84))
pins: 1 GND (power), 2 A13-I/O (io), 3 A6-I/O (io), 4 A12-I/O (io), 5 A7-I/O (io), 6 NC, 7 NC, 8 A11-I/O (io), 9 A8-I/O (io), 10 A10-I/O (io), 11 A9-I/O (io), 12 ~{PWRDN} (in), 13 TCLKIN-I/O (io), 14 NC, 15 I/O (io), 16 I/O (io), 17 I/O (io), 18 I/O (io), 19 I/O (io), 20 I/O (io), 21 I/O (io), 22 VCC (power), 23 I/O (io), 24 I/O (io), 25 I/O (io), 26 I/O (io), 27 I/O (io), 28 I/O (io), 29 I/O (io), 30 I/O (io), 31 M1-~{RDATA} (out), 32 M0-RTRIG (in), 33 M2-I/O (io), 34 HDC-I/O (io), 35 I/O (io), 36 ~{LDC}-I/O (io), 37 I/O (io), 38 NC, 39 I/O (io), 40 I/O (io), 41 NC, 42 ~{INIT}-I/O (io), 43 GND (power), 44 I/O (io), 45 I/O (io), 46 I/O (io), 47 I/O (io), 48 I/O (io), 49 I/O (io), 50 NC, 51 NC, 52 I/O (io), 53 XTL2 (IN)-I/O (io), 54 ~{RESET} (in), 55 DONE-~{PROG} (out), 56 D7-I/O (io), 57 XTL1(OUT)-BCLKIN-I/O (io), 58 D6-I/O (io), 59 I/O (io), 60 D5-I/O (io), 61 ~{CS}0-I/O (io), 62 D4-I/O (io), 63 I/O (io), 64 VCC (power), 65 D3-I/O (io), 66 ~{CS}1-I/O (io), 67 D2-I/O (io), 68 I/O (io), 69 NC, 70 D1-I/O (io), 71 RDY/~{BUSY}-~{RCLK}-I/O (io), 72 DO-DIN-I/O (io), 73 DOUT-I/O (io), 74 CCLK (io), 75 A0-~{WS}-I/O (io), 76 A1-CS2-I/O (io), 77 A2-I/O (io), 78 A3-I/O (io), 79 NC, 80 NC, 81 A15-I/O (io), 82 A4-I/O (io), 83 A14-I/O (io), 84 A5-I/O (io)

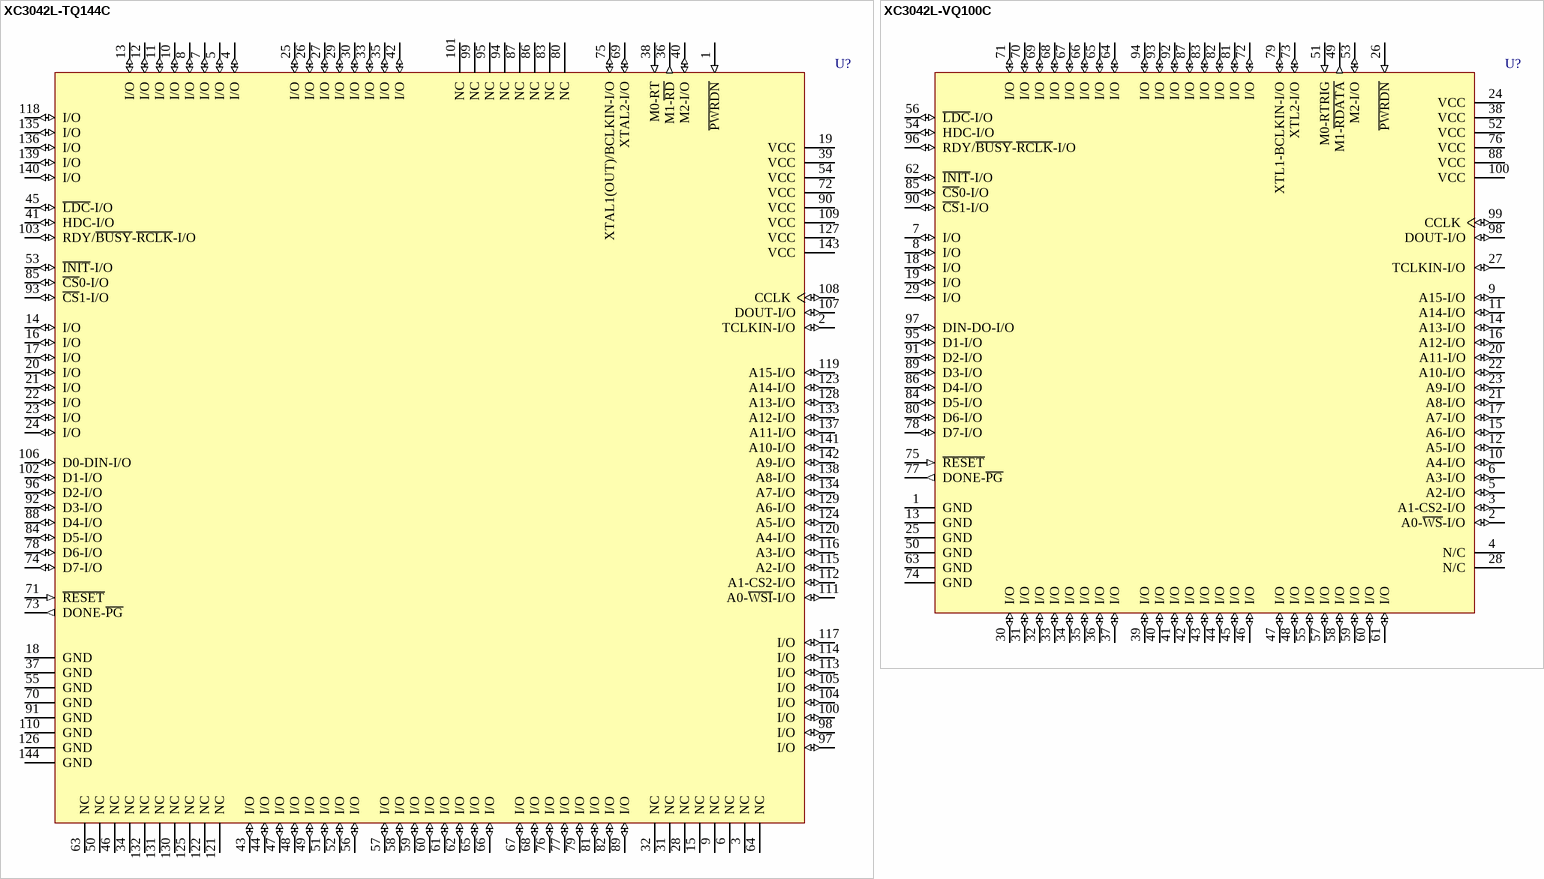
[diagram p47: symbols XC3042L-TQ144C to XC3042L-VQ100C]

## XC3042L-TQ144C
designator U?
Logic Cell Array with 144 CLBs, with 96 I/O Pinds, 144-Pin TQFP, Commercial Grade; ComponentAvailability: Not for New Design
footprint TQ144_N (Thin QFP, 144-Leads, Body 20x20mm, Pitch 0.5mm, IPC Medium Density)
footprint TQ144_L (Thin QFP, 144-Leads, Body 20x20mm, Pitch 0.5mm, IPC High Density)
footprint TQ144_M (Thin QFP, 144-Leads, Body 20x20mm, Pitch 0.5mm, IPC Low Density)
3D model XC3042L-TQ144 (144-Pin Thin Quad Flat Pack (TQ144))
pins: 1 ~{PWRDN} (in), 2 TCLKIN-I/O (io), 3 NC, 4 I/O (io), 5 I/O (io), 6 NC, 7 I/O (io), 8 I/O (io), 9 NC, 10 I/O (io), 11 I/O (io), 12 I/O (io), 13 I/O (io), 14 I/O (io), 15 NC, 16 I/O (io), 17 I/O (io), 18 GND (power), 19 VCC (power), 20 I/O (io), 21 I/O (io), 22 I/O (io), 23 I/O (io), 24 I/O (io), 25 I/O (io), 26 I/O (io), 27 I/O (io), 28 NC, 29 I/O (io), 30 I/O (io), 31 NC, 32 NC, 33 I/O (io), 34 NC, 35 I/O (io), 36 M1-~{RD} (out), 37 GND (power), 38 M0-RT (in), 39 VCC (power), 40 M2-I/O (io), 41 HDC-I/O (io), 42 I/O (io), 43 I/O (io), 44 I/O (io), 45 ~{LDC}-I/O (io), 46 NC, 47 I/O (io), 48 I/O (io), 49 I/O (io), 50 NC, 51 I/O (io), 52 I/O (io), 53 ~{INIT}-I/O (io), 54 VCC (power), 55 GND (power), 56 I/O (io), 57 I/O (io), 58 I/O (io), 59 I/O (io), 60 I/O (io), 61 I/O (io), 62 I/O (io), 63 NC, 64 NC, 65 I/O (io), 66 I/O (io), 67 I/O (io), 68 I/O (io), 69 XTAL2-I/O (io), 70 GND (power), 71 ~{RESET} (in), 72 VCC (power), 73 DONE-~{PG} (out), 74 D7-I/O (io), 75 XTAL1(OUT)/BCLKIN-I/O (io), 76 I/O (io), 77 I/O (io), 78 D6-I/O (io), 79 I/O (io), 80 NC, 81 I/O (io), 82 I/O (io), 83 NC, 84 D5-I/O (io), 85 ~{CS}0-I/O (io), 86 NC, 87 NC, 88 D4-I/O (io), 89 I/O (io), 90 VCC (power), 91 GND (power), 92 D3-I/O (io), 93 ~{CS}1-I/O (io), 94 NC, 95 NC, 96 D2-I/O (io), 97 I/O (io), 98 I/O (io), 99 NC, 100 I/O (io), 101 NC, 102 D1-I/O (io), 103 RDY/~{BUSY}-~{RCLK}-I/O (io), 104 I/O (io), 105 I/O (io), 106 D0-DIN-I/O (io), 107 DOUT-I/O (io), 108 CCLK (io), 109 VCC (power), 110 GND (power), 111 A0-~{WSI}-I/O (io), 112 A1-CS2-I/O (io), 113 I/O (io), 114 I/O (io), 115 A2-I/O (io), 116 A3-I/O (io), 117 I/O (io), 118 I/O (io), 119 A15-I/O (io), 120 A4-I/O (io), 121 NC, 122 NC, 123 A14-I/O (io), 124 A5-I/O (io), 125 NC, 126 GND (power), 127 VCC (power), 128 A13-I/O (io), 129 A6-I/O (io), 130 NC, 131 NC, 132 NC, 133 A12-I/O (io), 134 A7-I/O (io), 135 I/O (io), 136 I/O (io), 137 A11-I/O (io), 138 A8-I/O (io), 139 I/O (io), 140 I/O (io), 141 A10-I/O (io), 142 A9-I/O (io), 143 VCC (power), 144 GND (power)

## XC3042L-VQ100C
designator U?
Logic Cell Array with 144 CLBs, with 80 I/O Pins, 100-Pin VQFP, Commercial Grade; ComponentAvailability: Not for New Design
footprint VQ100_N (Thin QFP, 100-Leads, Body 14x14mm, Pitch 0.5mm, IPC Medium Density)
footprint VQ100_L (Thin QFP, 100-Leads, Body 14x14mm, Pitch 0.5mm, IPC High Density)
footprint VQ100_M (Thin QFP, 100-Leads, Body 14x14mm, Pitch 0.5mm, IPC Low Density)
3D model XC3042L-VQ100 (100-Pin Very Thin Quad Flat Pack (VQ100))
pins: 1 GND (power), 2 A0-~{WS}-I/O (io), 3 A1-CS2-I/O (io), 4 N/C, 5 A2-I/O (io), 6 A3-I/O (io), 7 I/O (io), 8 I/O (io), 9 A15-I/O (io), 10 A4-I/O (io), 11 A14-I/O (io), 12 A5-I/O (io), 13 GND (power), 14 A13-I/O (io), 15 A6-I/O (io), 16 A12-I/O (io), 17 A7-I/O (io), 18 I/O (io), 19 I/O (io), 20 A11-I/O (io), 21 A8-I/O (io), 22 A10-I/O (io), 23 A9-I/O (io), 24 VCC (power), 25 GND (power), 26 ~{PWRDN} (in), 27 TCLKIN-I/O (io), 28 N/C, 29 I/O (io), 30 I/O (io), 31 I/O (io), 32 I/O (io), 33 I/O (io), 34 I/O (io), 35 I/O (io), 36 I/O (io), 37 I/O (io), 38 VCC (power), 39 I/O (io), 40 I/O (io), 41 I/O (io), 42 I/O (io), 43 I/O (io), 44 I/O (io), 45 I/O (io), 46 I/O (io), 47 I/O (io), 48 I/O (io), 49 M1-~{RDATA} (out), 50 GND (power), 51 M0-RTRIG (in), 52 VCC (power), 53 M2-I/O (io), 54 HDC-I/O (io), 55 I/O (io), 56 ~{LDC}-I/O (io), 57 I/O (io), 58 I/O (io), 59 I/O (io), 60 I/O (io), 61 I/O (io), 62 ~{INIT}-I/O (io), 63 GND (power), 64 I/O (io), 65 I/O (io), 66 I/O (io), 67 I/O (io), 68 I/O (io), 69 I/O (io), 70 I/O (io), 71 I/O (io), 72 I/O (io), 73 XTL2-I/O (io), 74 GND (power), 75 ~{RESET} (in), 76 VCC (power), 77 DONE-~{PG} (out), 78 D7-I/O (io), 79 XTL1-BCLKIN-I/O (io), 80 D6-I/O (io), 81 I/O (io), 82 I/O (io), 83 I/O (io), 84 D5-I/O (io), 85 ~{CS}0-I/O (io), 86 D4-I/O (io), 87 I/O (io), 88 VCC (power), 89 D3-I/O (io), 90 ~{CS}1-I/O (io), 91 D2-I/O (io), 92 I/O (io), 93 I/O (io), 94 I/O (io), 95 D1-I/O (io), 96 RDY/~{BUSY}-~{RCLK}-I/O (io), 97 DIN-DO-I/O (io), 98 DOUT-I/O (io), 99 CCLK (io), 100 VCC (power)

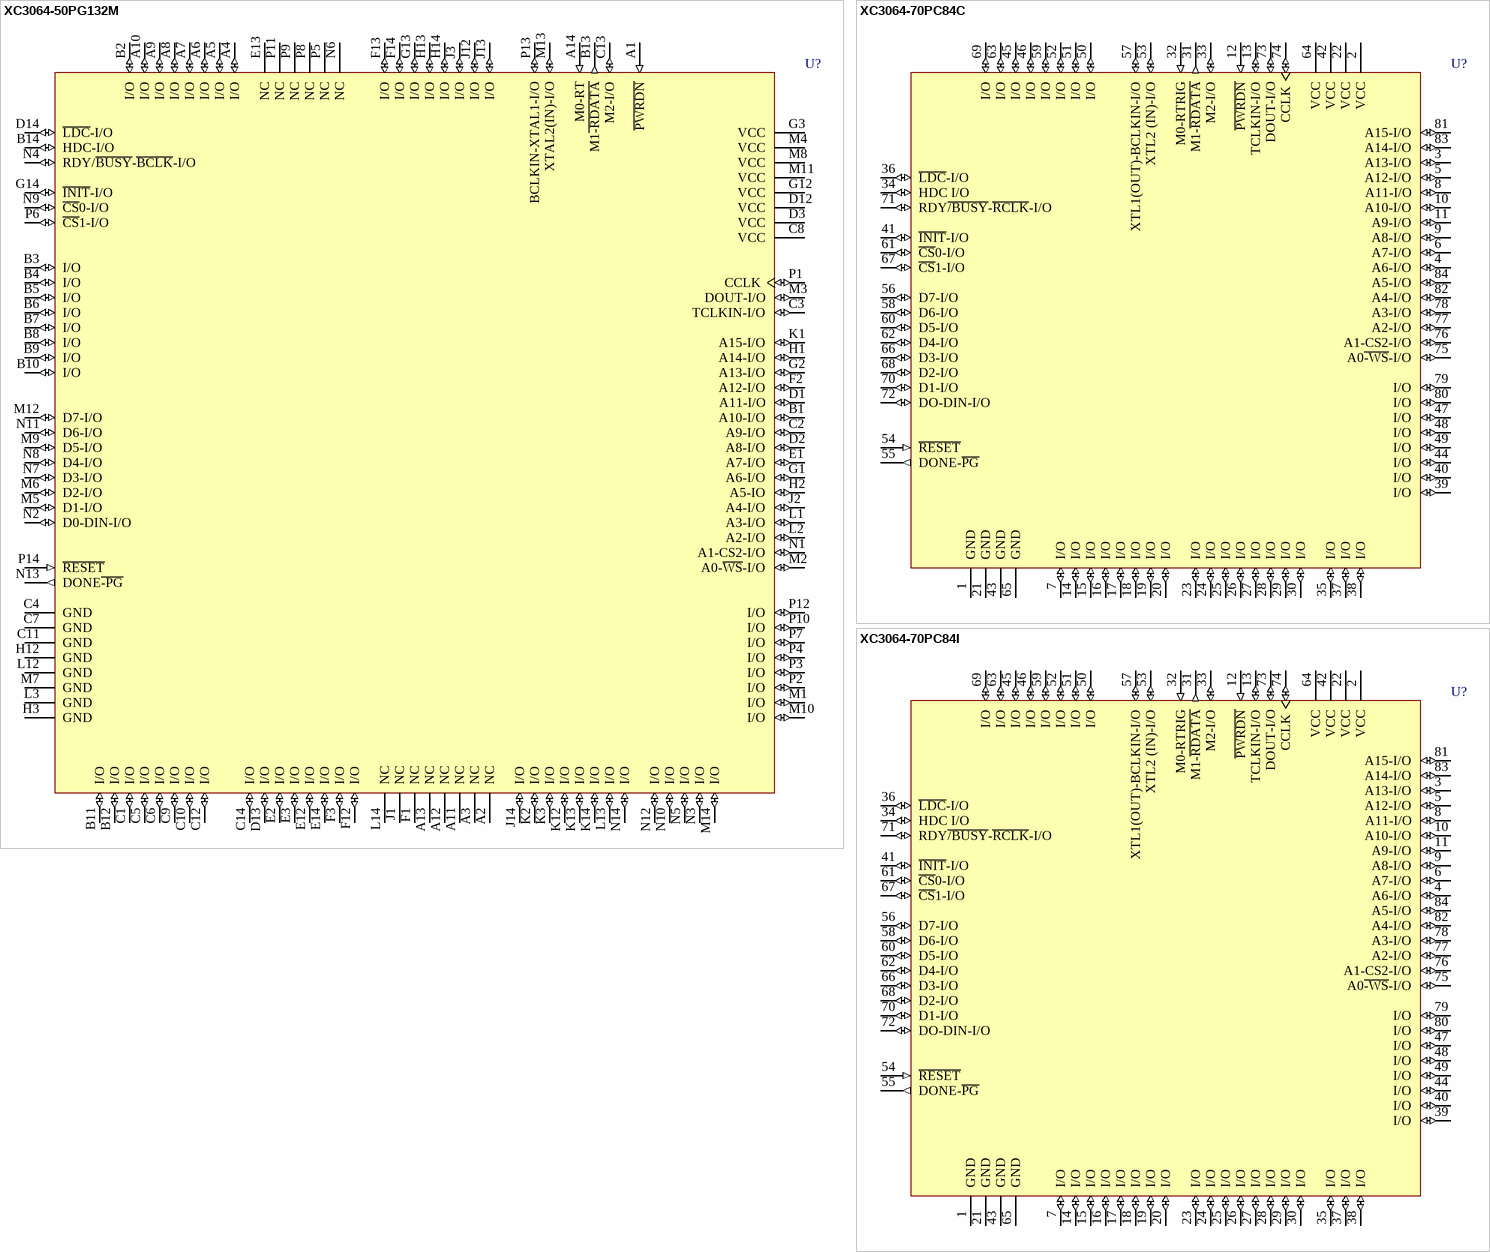
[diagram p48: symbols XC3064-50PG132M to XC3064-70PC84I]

## XC3064-50PG132M
designator U?
Logic Cell Array with 224 CLBs, with 96 I/O Pins, 132-Pin PGA, Military Grade; ComponentAvailability: Not for New Design
footprint PG132 (PGA, 132-Leads, Body 37x37mm, Pitch 2.54mm)
3D model XC3064-PG132 (132-Pin Ceramic Pin Grid Array (PG132))
pins: A1 ~{PWRDN} (in), A2 NC, A3 NC, A4 I/O (io), A5 I/O (io), A6 I/O (io), A7 I/O (io), A8 I/O (io), A9 I/O (io), A10 I/O (io), A11 NC, A12 NC, A13 NC, A14 M0-RT (in), B1 A10-I/O (io), B2 I/O (io), B3 I/O (io), B4 I/O (io), B5 I/O (io), B6 I/O (io), B7 I/O (io), B8 I/O (io), B9 I/O (io), B10 I/O (io), B11 I/O (io), B12 I/O (io), B13 M1~{-RDATA} (out), B14 HDC-I/O (io), C1 I/O (io), C2 A9-I/O (io), C3 TCLKIN-I/O (io), C4 GND (power), C5 I/O (io), C6 I/O (io), C7 GND (power), C8 VCC (power), C9 I/O (io), C10 I/O (io), C11 GND (power), C12 I/O (io), C13 M2-I/O (io), C14 I/O (io), D1 A11-I/O (io), D2 A8-I/O (io), D3 VCC (power), D12 VCC (power), D13 I/O (io), D14 ~{LDC}-I/O (io), E1 A7-I/O (io), E2 I/O (io), E3 I/O (io), E12 I/O (io), E13 NC, E14 I/O (io), F1 NC, F2 A12-I/O (io), F3 I/O (io), F12 I/O (io), F13 I/O (io), F14 I/O (io), G1 A6-I/O (io), G2 A13-I/O (io), G3 VCC (power), G12 VCC (power), G13 I/O (io), G14 ~{INIT}-I/O (io), H1 A14-I/O (io), H2 A5-IO (io), H3 GND (power), H12 GND (power), H13 I/O (io), H14 I/O (io), J1 NC, J2 A4-I/O (io), J3 I/O (io), J12 I/O (io), J13 I/O (io), J14 I/O (io), K1 A15-I/O (io), K2 I/O (io), K3 I/O (io), K12 I/O (io), K13 I/O (io), K14 I/O (io), L1 A3-I/O (io), L2 A2-I/O (io), L3 GND (power), L12 GND (power), L13 I/O (io), L14 NC, M1 I/O (io), M2 A0-~{WS}-I/O (io), M3 DOUT-I/O (io), M4 VCC (power), M5 D1-I/O (io), M6 D2-I/O (io), M7 GND (power), M8 VCC (power), M9 D5-I/O (io), M10 I/O (io), M11 VCC (power), M12 D7-I/O (io), M13 XTAL2(IN)-I/O (io), M14 I/O (io), N1 A1-CS2-I/O (io), N2 D0-DIN-I/O (io), N3 I/O (io), N4 RDY/~{BUSY}-~{BCLK}-I/O (io), N5 I/O (io), N6 NC, N7 D3-I/O (io), N8 D4-I/O (io), N9 ~{CS}0-I/O (io), N10 I/O (io), N11 D6-I/O (io), N12 I/O (io), N13 DONE~{-PG} (out), N14 I/O (io), P1 CCLK (io), P2 I/O (io), P3 I/O (io), P4 I/O (io), P5 NC, P6 ~{CS}1-I/O (io), P7 I/O (io), P8 NC, P9 NC, P10 I/O (io), P11 NC, P12 I/O (io), P13 BCLKIN-XTAL1-I/O (io), P14 ~{RESET} (in)

## XC3064-70PC84C
designator U?
Logic Cell Array with 224 CLBs, with 70 I/O Pins, 84-Pin PLCC, Commercial Grade; ComponentAvailability: Not for New Design
footprint PC84_N (Leaded Chip Carrier, 84-Leads, Body 29.3x29.3mm, Pitch 1.27mm, IPC Medium Density)
footprint PC84_L (Leaded Chip Carrier, 84-Leads, Body 29.3x29.3mm, Pitch 1.27mm, IPC High Density)
footprint PC84_M (Leaded Chip Carrier, 84-Leads, Body 29.3x29.3mm, Pitch 1.27mm, IPC Low Density)
3D model XC3064-PC84 (84-Pin Plastic Leaded Chip Carrier (PC84))
pins: 1 GND (power), 2 VCC (power), 3 A13-I/O (io), 4 A6-I/O (io), 5 A12-I/O (io), 6 A7-I/O (io), 7 I/O (io), 8 A11-I/O (io), 9 A8-I/O (io), 10 A10-I/O (io), 11 A9-I/O (io), 12 ~{PWRDN} (in), 13 TCLKIN-I/O (io), 14 I/O (io), 15 I/O (io), 16 I/O (io), 17 I/O (io), 18 I/O (io), 19 I/O (io), 20 I/O (io), 21 GND (power), 22 VCC (power), 23 I/O (io), 24 I/O (io), 25 I/O (io), 26 I/O (io), 27 I/O (io), 28 I/O (io), 29 I/O (io), 30 I/O (io), 31 M1-~{RDATA} (out), 32 M0-RTRIG (in), 33 M2-I/O (io), 34 HDC I/O (io), 35 I/O (io), 36 ~{LDC}-I/O (io), 37 I/O (io), 38 I/O (io), 39 I/O (io), 40 I/O (io), 41 ~{INIT}-I/O (io), 42 VCC (power), 43 GND (power), 44 I/O (io), 45 I/O (io), 46 I/O (io), 47 I/O (io), 48 I/O (io), 49 I/O (io), 50 I/O (io), 51 I/O (io), 52 I/O (io), 53 XTL2 (IN)-I/O (io), 54 ~{RESET} (in), 55 DONE-~{PG} (out), 56 D7-I/O (io), 57 XTL1(OUT)-BCLKIN-I/O (io), 58 D6-I/O (io), 59 I/O (io), 60 D5-I/O (io), 61 ~{CS}0-I/O (io), 62 D4-I/O (io), 63 I/O (io), 64 VCC (power), 65 GND (power), 66 D3-I/O (io), 67 ~{CS}1-I/O (io), 68 D2-I/O (io), 69 I/O (io), 70 D1-I/O (io), 71 RDY~{/BUSY}-~{RCLK}-I/O (io), 72 DO-DIN-I/O (io), 73 DOUT-I/O (io), 74 CCLK (io), 75 A0~{-WS}-I/O (io), 76 A1-CS2-I/O (io), 77 A2-I/O (io), 78 A3-I/O (io), 79 I/O (io), 80 I/O (io), 81 A15-I/O (io), 82 A4-I/O (io), 83 A14-I/O (io), 84 A5-I/O (io)

## XC3064-70PC84I
designator U?
Logic Cell Array with 224 CLBs, with 70 I/O Pins, 84-Pin PLCC, Industrial Grade; ComponentAvailability: Not for New Design
footprint PC84_N (Leaded Chip Carrier, 84-Leads, Body 29.3x29.3mm, Pitch 1.27mm, IPC Medium Density)
footprint PC84_L (Leaded Chip Carrier, 84-Leads, Body 29.3x29.3mm, Pitch 1.27mm, IPC High Density)
footprint PC84_M (Leaded Chip Carrier, 84-Leads, Body 29.3x29.3mm, Pitch 1.27mm, IPC Low Density)
3D model XC3064-PC84 (84-Pin Plastic Leaded Chip Carrier (PC84))
pins: 1 GND (power), 2 VCC (power), 3 A13-I/O (io), 4 A6-I/O (io), 5 A12-I/O (io), 6 A7-I/O (io), 7 I/O (io), 8 A11-I/O (io), 9 A8-I/O (io), 10 A10-I/O (io), 11 A9-I/O (io), 12 ~{PWRDN} (in), 13 TCLKIN-I/O (io), 14 I/O (io), 15 I/O (io), 16 I/O (io), 17 I/O (io), 18 I/O (io), 19 I/O (io), 20 I/O (io), 21 GND (power), 22 VCC (power), 23 I/O (io), 24 I/O (io), 25 I/O (io), 26 I/O (io), 27 I/O (io), 28 I/O (io), 29 I/O (io), 30 I/O (io), 31 M1-~{RDATA} (out), 32 M0-RTRIG (in), 33 M2-I/O (io), 34 HDC I/O (io), 35 I/O (io), 36 ~{LDC}-I/O (io), 37 I/O (io), 38 I/O (io), 39 I/O (io), 40 I/O (io), 41 ~{INIT}-I/O (io), 42 VCC (power), 43 GND (power), 44 I/O (io), 45 I/O (io), 46 I/O (io), 47 I/O (io), 48 I/O (io), 49 I/O (io), 50 I/O (io), 51 I/O (io), 52 I/O (io), 53 XTL2 (IN)-I/O (io), 54 ~{RESET} (in), 55 DONE-~{PG} (out), 56 D7-I/O (io), 57 XTL1(OUT)-BCLKIN-I/O (io), 58 D6-I/O (io), 59 I/O (io), 60 D5-I/O (io), 61 ~{CS}0-I/O (io), 62 D4-I/O (io), 63 I/O (io), 64 VCC (power), 65 GND (power), 66 D3-I/O (io), 67 ~{CS}1-I/O (io), 68 D2-I/O (io), 69 I/O (io), 70 D1-I/O (io), 71 RDY~{/BUSY}-~{RCLK}-I/O (io), 72 DO-DIN-I/O (io), 73 DOUT-I/O (io), 74 CCLK (io), 75 A0~{-WS}-I/O (io), 76 A1-CS2-I/O (io), 77 A2-I/O (io), 78 A3-I/O (io), 79 I/O (io), 80 I/O (io), 81 A15-I/O (io), 82 A4-I/O (io), 83 A14-I/O (io), 84 A5-I/O (io)

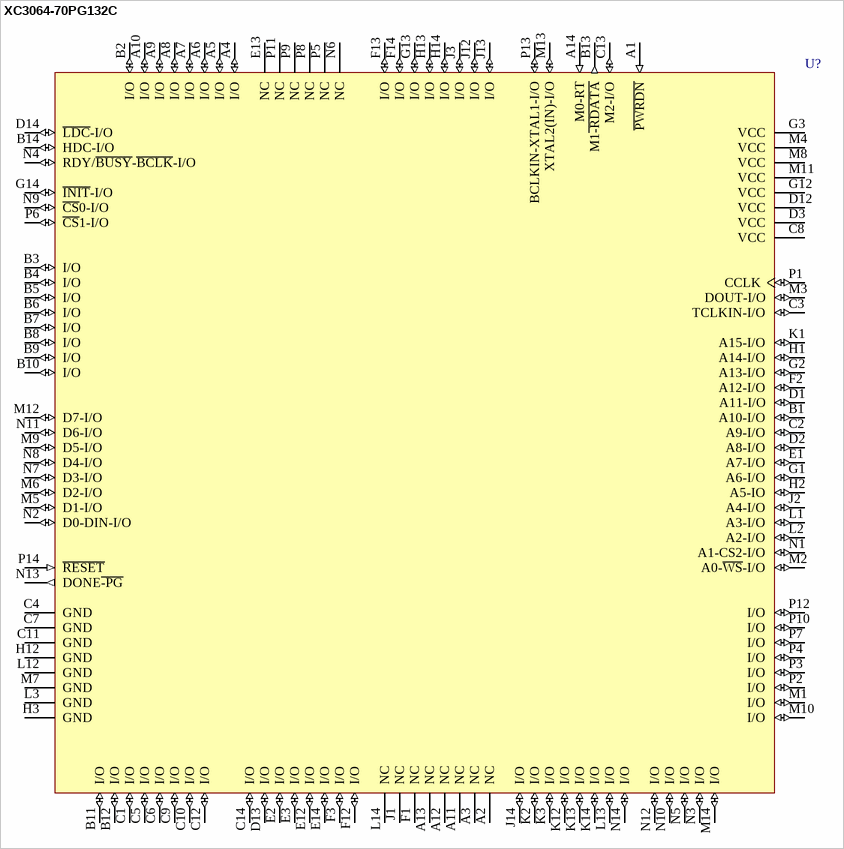
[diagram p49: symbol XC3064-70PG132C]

## XC3064-70PG132C
designator U?
Logic Cell Array with 224 CLBs, with 96 I/O Pins, 132-Pin PGA, Commercial Grade; ComponentAvailability: Not for New Design
footprint PG132 (PGA, 132-Leads, Body 37x37mm, Pitch 2.54mm)
3D model XC3064-PG132 (132-Pin Ceramic Pin Grid Array (PG132))
pins: A1 ~{PWRDN} (in), A2 NC, A3 NC, A4 I/O (io), A5 I/O (io), A6 I/O (io), A7 I/O (io), A8 I/O (io), A9 I/O (io), A10 I/O (io), A11 NC, A12 NC, A13 NC, A14 M0-RT (in), B1 A10-I/O (io), B2 I/O (io), B3 I/O (io), B4 I/O (io), B5 I/O (io), B6 I/O (io), B7 I/O (io), B8 I/O (io), B9 I/O (io), B10 I/O (io), B11 I/O (io), B12 I/O (io), B13 M1~{-RDATA} (out), B14 HDC-I/O (io), C1 I/O (io), C2 A9-I/O (io), C3 TCLKIN-I/O (io), C4 GND (power), C5 I/O (io), C6 I/O (io), C7 GND (power), C8 VCC (power), C9 I/O (io), C10 I/O (io), C11 GND (power), C12 I/O (io), C13 M2-I/O (io), C14 I/O (io), D1 A11-I/O (io), D2 A8-I/O (io), D3 VCC (power), D12 VCC (power), D13 I/O (io), D14 ~{LDC}-I/O (io), E1 A7-I/O (io), E2 I/O (io), E3 I/O (io), E12 I/O (io), E13 NC, E14 I/O (io), F1 NC, F2 A12-I/O (io), F3 I/O (io), F12 I/O (io), F13 I/O (io), F14 I/O (io), G1 A6-I/O (io), G2 A13-I/O (io), G3 VCC (power), G12 VCC (power), G13 I/O (io), G14 ~{INIT}-I/O (io), H1 A14-I/O (io), H2 A5-IO (io), H3 GND (power), H12 GND (power), H13 I/O (io), H14 I/O (io), J1 NC, J2 A4-I/O (io), J3 I/O (io), J12 I/O (io), J13 I/O (io), J14 I/O (io), K1 A15-I/O (io), K2 I/O (io), K3 I/O (io), K12 I/O (io), K13 I/O (io), K14 I/O (io), L1 A3-I/O (io), L2 A2-I/O (io), L3 GND (power), L12 GND (power), L13 I/O (io), L14 NC, M1 I/O (io), M2 A0-~{WS}-I/O (io), M3 DOUT-I/O (io), M4 VCC (power), M5 D1-I/O (io), M6 D2-I/O (io), M7 GND (power), M8 VCC (power), M9 D5-I/O (io), M10 I/O (io), M11 VCC (power), M12 D7-I/O (io), M13 XTAL2(IN)-I/O (io), M14 I/O (io), N1 A1-CS2-I/O (io), N2 D0-DIN-I/O (io), N3 I/O (io), N4 RDY/~{BUSY}-~{BCLK}-I/O (io), N5 I/O (io), N6 NC, N7 D3-I/O (io), N8 D4-I/O (io), N9 ~{CS}0-I/O (io), N10 I/O (io), N11 D6-I/O (io), N12 I/O (io), N13 DONE~{-PG} (out), N14 I/O (io), P1 CCLK (io), P2 I/O (io), P3 I/O (io), P4 I/O (io), P5 NC, P6 ~{CS}1-I/O (io), P7 I/O (io), P8 NC, P9 NC, P10 I/O (io), P11 NC, P12 I/O (io), P13 BCLKIN-XTAL1-I/O (io), P14 ~{RESET} (in)

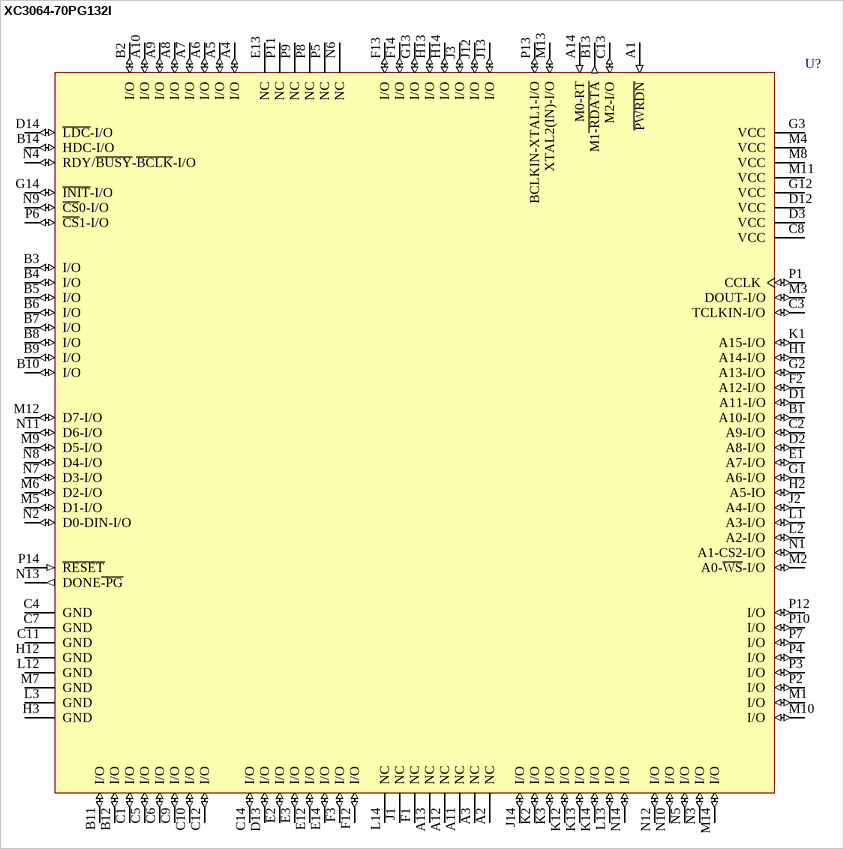
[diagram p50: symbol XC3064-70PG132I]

## XC3064-70PG132I
designator U?
Logic Cell Array with 224 CLBs, with 96 I/O Pins, 132-Pin PGA, Industrial Grade; ComponentAvailability: Not for New Design
footprint PG132 (PGA, 132-Leads, Body 37x37mm, Pitch 2.54mm)
3D model XC3064-PG132 (132-Pin Ceramic Pin Grid Array (PG132))
pins: A1 ~{PWRDN} (in), A2 NC, A3 NC, A4 I/O (io), A5 I/O (io), A6 I/O (io), A7 I/O (io), A8 I/O (io), A9 I/O (io), A10 I/O (io), A11 NC, A12 NC, A13 NC, A14 M0-RT (in), B1 A10-I/O (io), B2 I/O (io), B3 I/O (io), B4 I/O (io), B5 I/O (io), B6 I/O (io), B7 I/O (io), B8 I/O (io), B9 I/O (io), B10 I/O (io), B11 I/O (io), B12 I/O (io), B13 M1~{-RDATA} (out), B14 HDC-I/O (io), C1 I/O (io), C2 A9-I/O (io), C3 TCLKIN-I/O (io), C4 GND (power), C5 I/O (io), C6 I/O (io), C7 GND (power), C8 VCC (power), C9 I/O (io), C10 I/O (io), C11 GND (power), C12 I/O (io), C13 M2-I/O (io), C14 I/O (io), D1 A11-I/O (io), D2 A8-I/O (io), D3 VCC (power), D12 VCC (power), D13 I/O (io), D14 ~{LDC}-I/O (io), E1 A7-I/O (io), E2 I/O (io), E3 I/O (io), E12 I/O (io), E13 NC, E14 I/O (io), F1 NC, F2 A12-I/O (io), F3 I/O (io), F12 I/O (io), F13 I/O (io), F14 I/O (io), G1 A6-I/O (io), G2 A13-I/O (io), G3 VCC (power), G12 VCC (power), G13 I/O (io), G14 ~{INIT}-I/O (io), H1 A14-I/O (io), H2 A5-IO (io), H3 GND (power), H12 GND (power), H13 I/O (io), H14 I/O (io), J1 NC, J2 A4-I/O (io), J3 I/O (io), J12 I/O (io), J13 I/O (io), J14 I/O (io), K1 A15-I/O (io), K2 I/O (io), K3 I/O (io), K12 I/O (io), K13 I/O (io), K14 I/O (io), L1 A3-I/O (io), L2 A2-I/O (io), L3 GND (power), L12 GND (power), L13 I/O (io), L14 NC, M1 I/O (io), M2 A0-~{WS}-I/O (io), M3 DOUT-I/O (io), M4 VCC (power), M5 D1-I/O (io), M6 D2-I/O (io), M7 GND (power), M8 VCC (power), M9 D5-I/O (io), M10 I/O (io), M11 VCC (power), M12 D7-I/O (io), M13 XTAL2(IN)-I/O (io), M14 I/O (io), N1 A1-CS2-I/O (io), N2 D0-DIN-I/O (io), N3 I/O (io), N4 RDY/~{BUSY}-~{BCLK}-I/O (io), N5 I/O (io), N6 NC, N7 D3-I/O (io), N8 D4-I/O (io), N9 ~{CS}0-I/O (io), N10 I/O (io), N11 D6-I/O (io), N12 I/O (io), N13 DONE~{-PG} (out), N14 I/O (io), P1 CCLK (io), P2 I/O (io), P3 I/O (io), P4 I/O (io), P5 NC, P6 ~{CS}1-I/O (io), P7 I/O (io), P8 NC, P9 NC, P10 I/O (io), P11 NC, P12 I/O (io), P13 BCLKIN-XTAL1-I/O (io), P14 ~{RESET} (in)

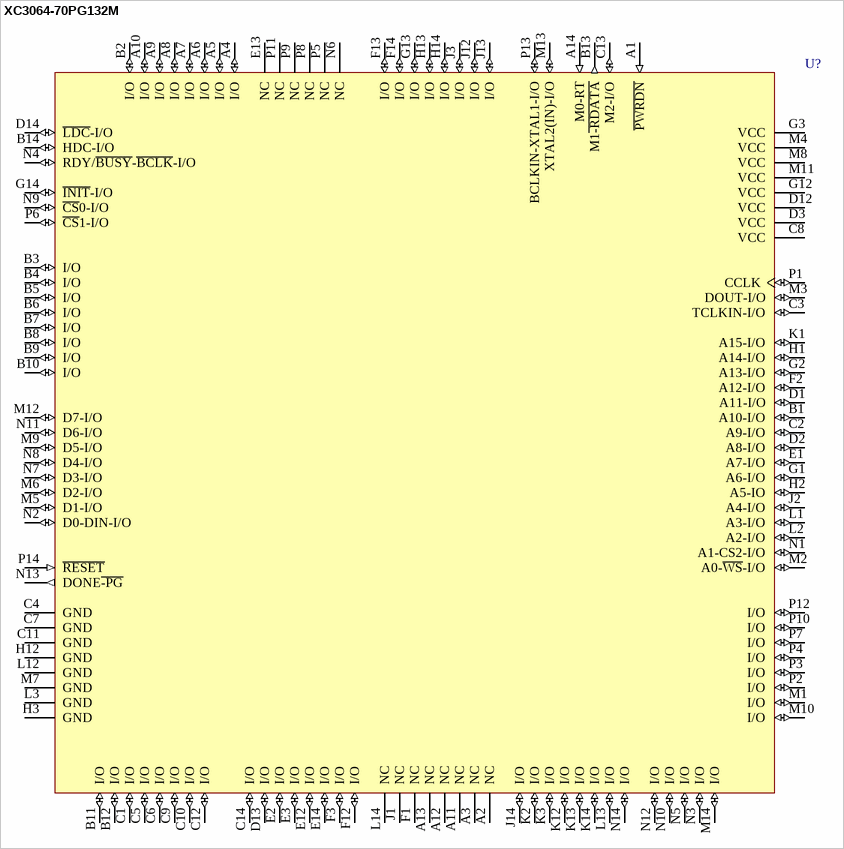
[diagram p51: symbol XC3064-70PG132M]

## XC3064-70PG132M
designator U?
Logic Cell Array with 224 CLBs, with 96 I/O Pins, 132-Pin PGA, Military Grade; ComponentAvailability: Not for New Design
footprint PG132 (PGA, 132-Leads, Body 37x37mm, Pitch 2.54mm)
3D model XC3064-PG132 (132-Pin Ceramic Pin Grid Array (PG132))
pins: A1 ~{PWRDN} (in), A2 NC, A3 NC, A4 I/O (io), A5 I/O (io), A6 I/O (io), A7 I/O (io), A8 I/O (io), A9 I/O (io), A10 I/O (io), A11 NC, A12 NC, A13 NC, A14 M0-RT (in), B1 A10-I/O (io), B2 I/O (io), B3 I/O (io), B4 I/O (io), B5 I/O (io), B6 I/O (io), B7 I/O (io), B8 I/O (io), B9 I/O (io), B10 I/O (io), B11 I/O (io), B12 I/O (io), B13 M1~{-RDATA} (out), B14 HDC-I/O (io), C1 I/O (io), C2 A9-I/O (io), C3 TCLKIN-I/O (io), C4 GND (power), C5 I/O (io), C6 I/O (io), C7 GND (power), C8 VCC (power), C9 I/O (io), C10 I/O (io), C11 GND (power), C12 I/O (io), C13 M2-I/O (io), C14 I/O (io), D1 A11-I/O (io), D2 A8-I/O (io), D3 VCC (power), D12 VCC (power), D13 I/O (io), D14 ~{LDC}-I/O (io), E1 A7-I/O (io), E2 I/O (io), E3 I/O (io), E12 I/O (io), E13 NC, E14 I/O (io), F1 NC, F2 A12-I/O (io), F3 I/O (io), F12 I/O (io), F13 I/O (io), F14 I/O (io), G1 A6-I/O (io), G2 A13-I/O (io), G3 VCC (power), G12 VCC (power), G13 I/O (io), G14 ~{INIT}-I/O (io), H1 A14-I/O (io), H2 A5-IO (io), H3 GND (power), H12 GND (power), H13 I/O (io), H14 I/O (io), J1 NC, J2 A4-I/O (io), J3 I/O (io), J12 I/O (io), J13 I/O (io), J14 I/O (io), K1 A15-I/O (io), K2 I/O (io), K3 I/O (io), K12 I/O (io), K13 I/O (io), K14 I/O (io), L1 A3-I/O (io), L2 A2-I/O (io), L3 GND (power), L12 GND (power), L13 I/O (io), L14 NC, M1 I/O (io), M2 A0-~{WS}-I/O (io), M3 DOUT-I/O (io), M4 VCC (power), M5 D1-I/O (io), M6 D2-I/O (io), M7 GND (power), M8 VCC (power), M9 D5-I/O (io), M10 I/O (io), M11 VCC (power), M12 D7-I/O (io), M13 XTAL2(IN)-I/O (io), M14 I/O (io), N1 A1-CS2-I/O (io), N2 D0-DIN-I/O (io), N3 I/O (io), N4 RDY/~{BUSY}-~{BCLK}-I/O (io), N5 I/O (io), N6 NC, N7 D3-I/O (io), N8 D4-I/O (io), N9 ~{CS}0-I/O (io), N10 I/O (io), N11 D6-I/O (io), N12 I/O (io), N13 DONE~{-PG} (out), N14 I/O (io), P1 CCLK (io), P2 I/O (io), P3 I/O (io), P4 I/O (io), P5 NC, P6 ~{CS}1-I/O (io), P7 I/O (io), P8 NC, P9 NC, P10 I/O (io), P11 NC, P12 I/O (io), P13 BCLKIN-XTAL1-I/O (io), P14 ~{RESET} (in)

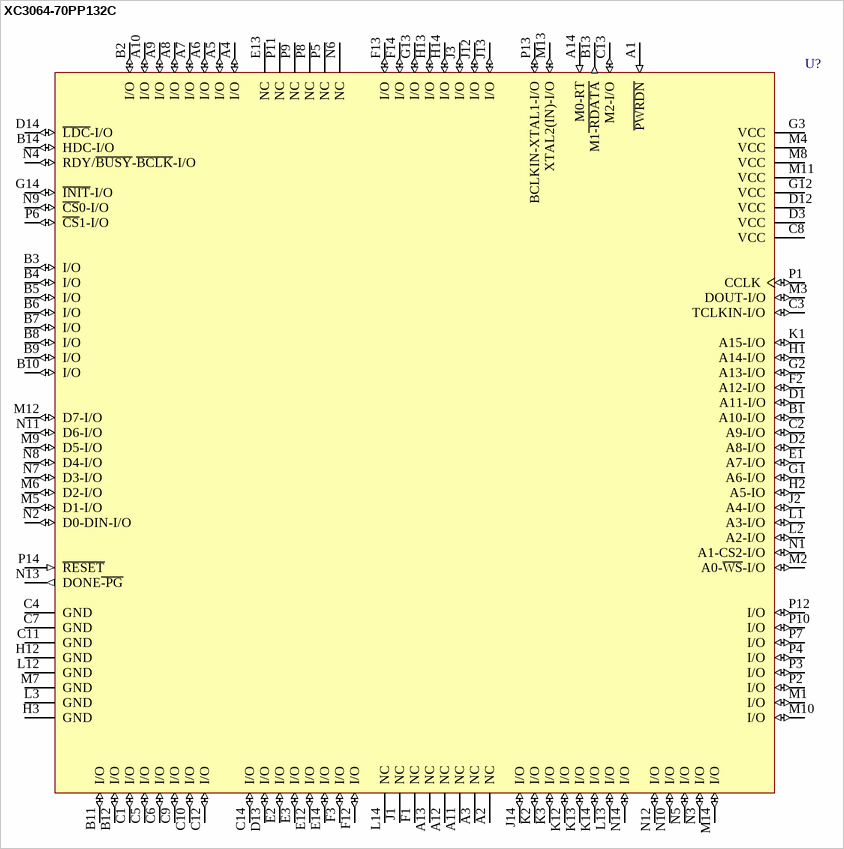
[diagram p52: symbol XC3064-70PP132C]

## XC3064-70PP132C
designator U?
Logic Cell Array with 224 CLBs, with 96 I/O Pins, 132-Pin PGA, Commercial Grade; ComponentAvailability: Not for New Design
footprint PP132 (PGA, 132-Leads, Body 37x37mm, Pitch 2.54mm)
3D model XC3064-PP132 (132-Pin Plastic Pin Grid Array (PP132))
pins: A1 ~{PWRDN} (in), A2 NC, A3 NC, A4 I/O (io), A5 I/O (io), A6 I/O (io), A7 I/O (io), A8 I/O (io), A9 I/O (io), A10 I/O (io), A11 NC, A12 NC, A13 NC, A14 M0-RT (in), B1 A10-I/O (io), B2 I/O (io), B3 I/O (io), B4 I/O (io), B5 I/O (io), B6 I/O (io), B7 I/O (io), B8 I/O (io), B9 I/O (io), B10 I/O (io), B11 I/O (io), B12 I/O (io), B13 M1~{-RDATA} (out), B14 HDC-I/O (io), C1 I/O (io), C2 A9-I/O (io), C3 TCLKIN-I/O (io), C4 GND (power), C5 I/O (io), C6 I/O (io), C7 GND (power), C8 VCC (power), C9 I/O (io), C10 I/O (io), C11 GND (power), C12 I/O (io), C13 M2-I/O (io), C14 I/O (io), D1 A11-I/O (io), D2 A8-I/O (io), D3 VCC (power), D12 VCC (power), D13 I/O (io), D14 ~{LDC}-I/O (io), E1 A7-I/O (io), E2 I/O (io), E3 I/O (io), E12 I/O (io), E13 NC, E14 I/O (io), F1 NC, F2 A12-I/O (io), F3 I/O (io), F12 I/O (io), F13 I/O (io), F14 I/O (io), G1 A6-I/O (io), G2 A13-I/O (io), G3 VCC (power), G12 VCC (power), G13 I/O (io), G14 ~{INIT}-I/O (io), H1 A14-I/O (io), H2 A5-IO (io), H3 GND (power), H12 GND (power), H13 I/O (io), H14 I/O (io), J1 NC, J2 A4-I/O (io), J3 I/O (io), J12 I/O (io), J13 I/O (io), J14 I/O (io), K1 A15-I/O (io), K2 I/O (io), K3 I/O (io), K12 I/O (io), K13 I/O (io), K14 I/O (io), L1 A3-I/O (io), L2 A2-I/O (io), L3 GND (power), L12 GND (power), L13 I/O (io), L14 NC, M1 I/O (io), M2 A0-~{WS}-I/O (io), M3 DOUT-I/O (io), M4 VCC (power), M5 D1-I/O (io), M6 D2-I/O (io), M7 GND (power), M8 VCC (power), M9 D5-I/O (io), M10 I/O (io), M11 VCC (power), M12 D7-I/O (io), M13 XTAL2(IN)-I/O (io), M14 I/O (io), N1 A1-CS2-I/O (io), N2 D0-DIN-I/O (io), N3 I/O (io), N4 RDY/~{BUSY}-~{BCLK}-I/O (io), N5 I/O (io), N6 NC, N7 D3-I/O (io), N8 D4-I/O (io), N9 ~{CS}0-I/O (io), N10 I/O (io), N11 D6-I/O (io), N12 I/O (io), N13 DONE~{-PG} (out), N14 I/O (io), P1 CCLK (io), P2 I/O (io), P3 I/O (io), P4 I/O (io), P5 NC, P6 ~{CS}1-I/O (io), P7 I/O (io), P8 NC, P9 NC, P10 I/O (io), P11 NC, P12 I/O (io), P13 BCLKIN-XTAL1-I/O (io), P14 ~{RESET} (in)

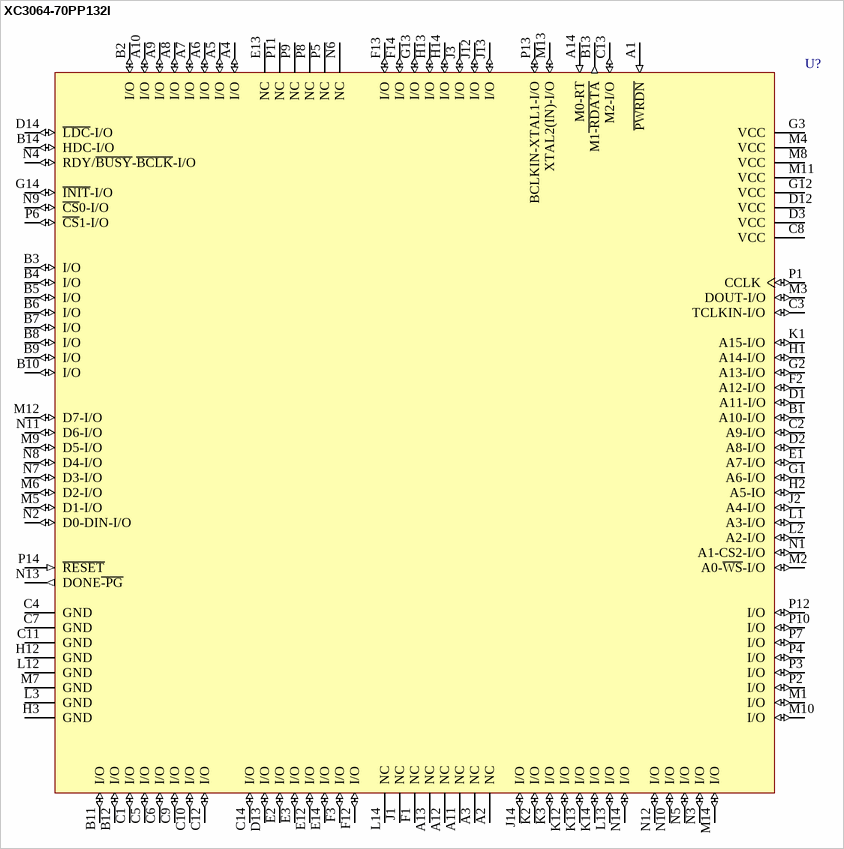
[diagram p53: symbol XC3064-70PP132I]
